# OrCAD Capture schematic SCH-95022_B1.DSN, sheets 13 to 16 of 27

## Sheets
13 Page14 USB3.0 TYPE-C DRP: size C
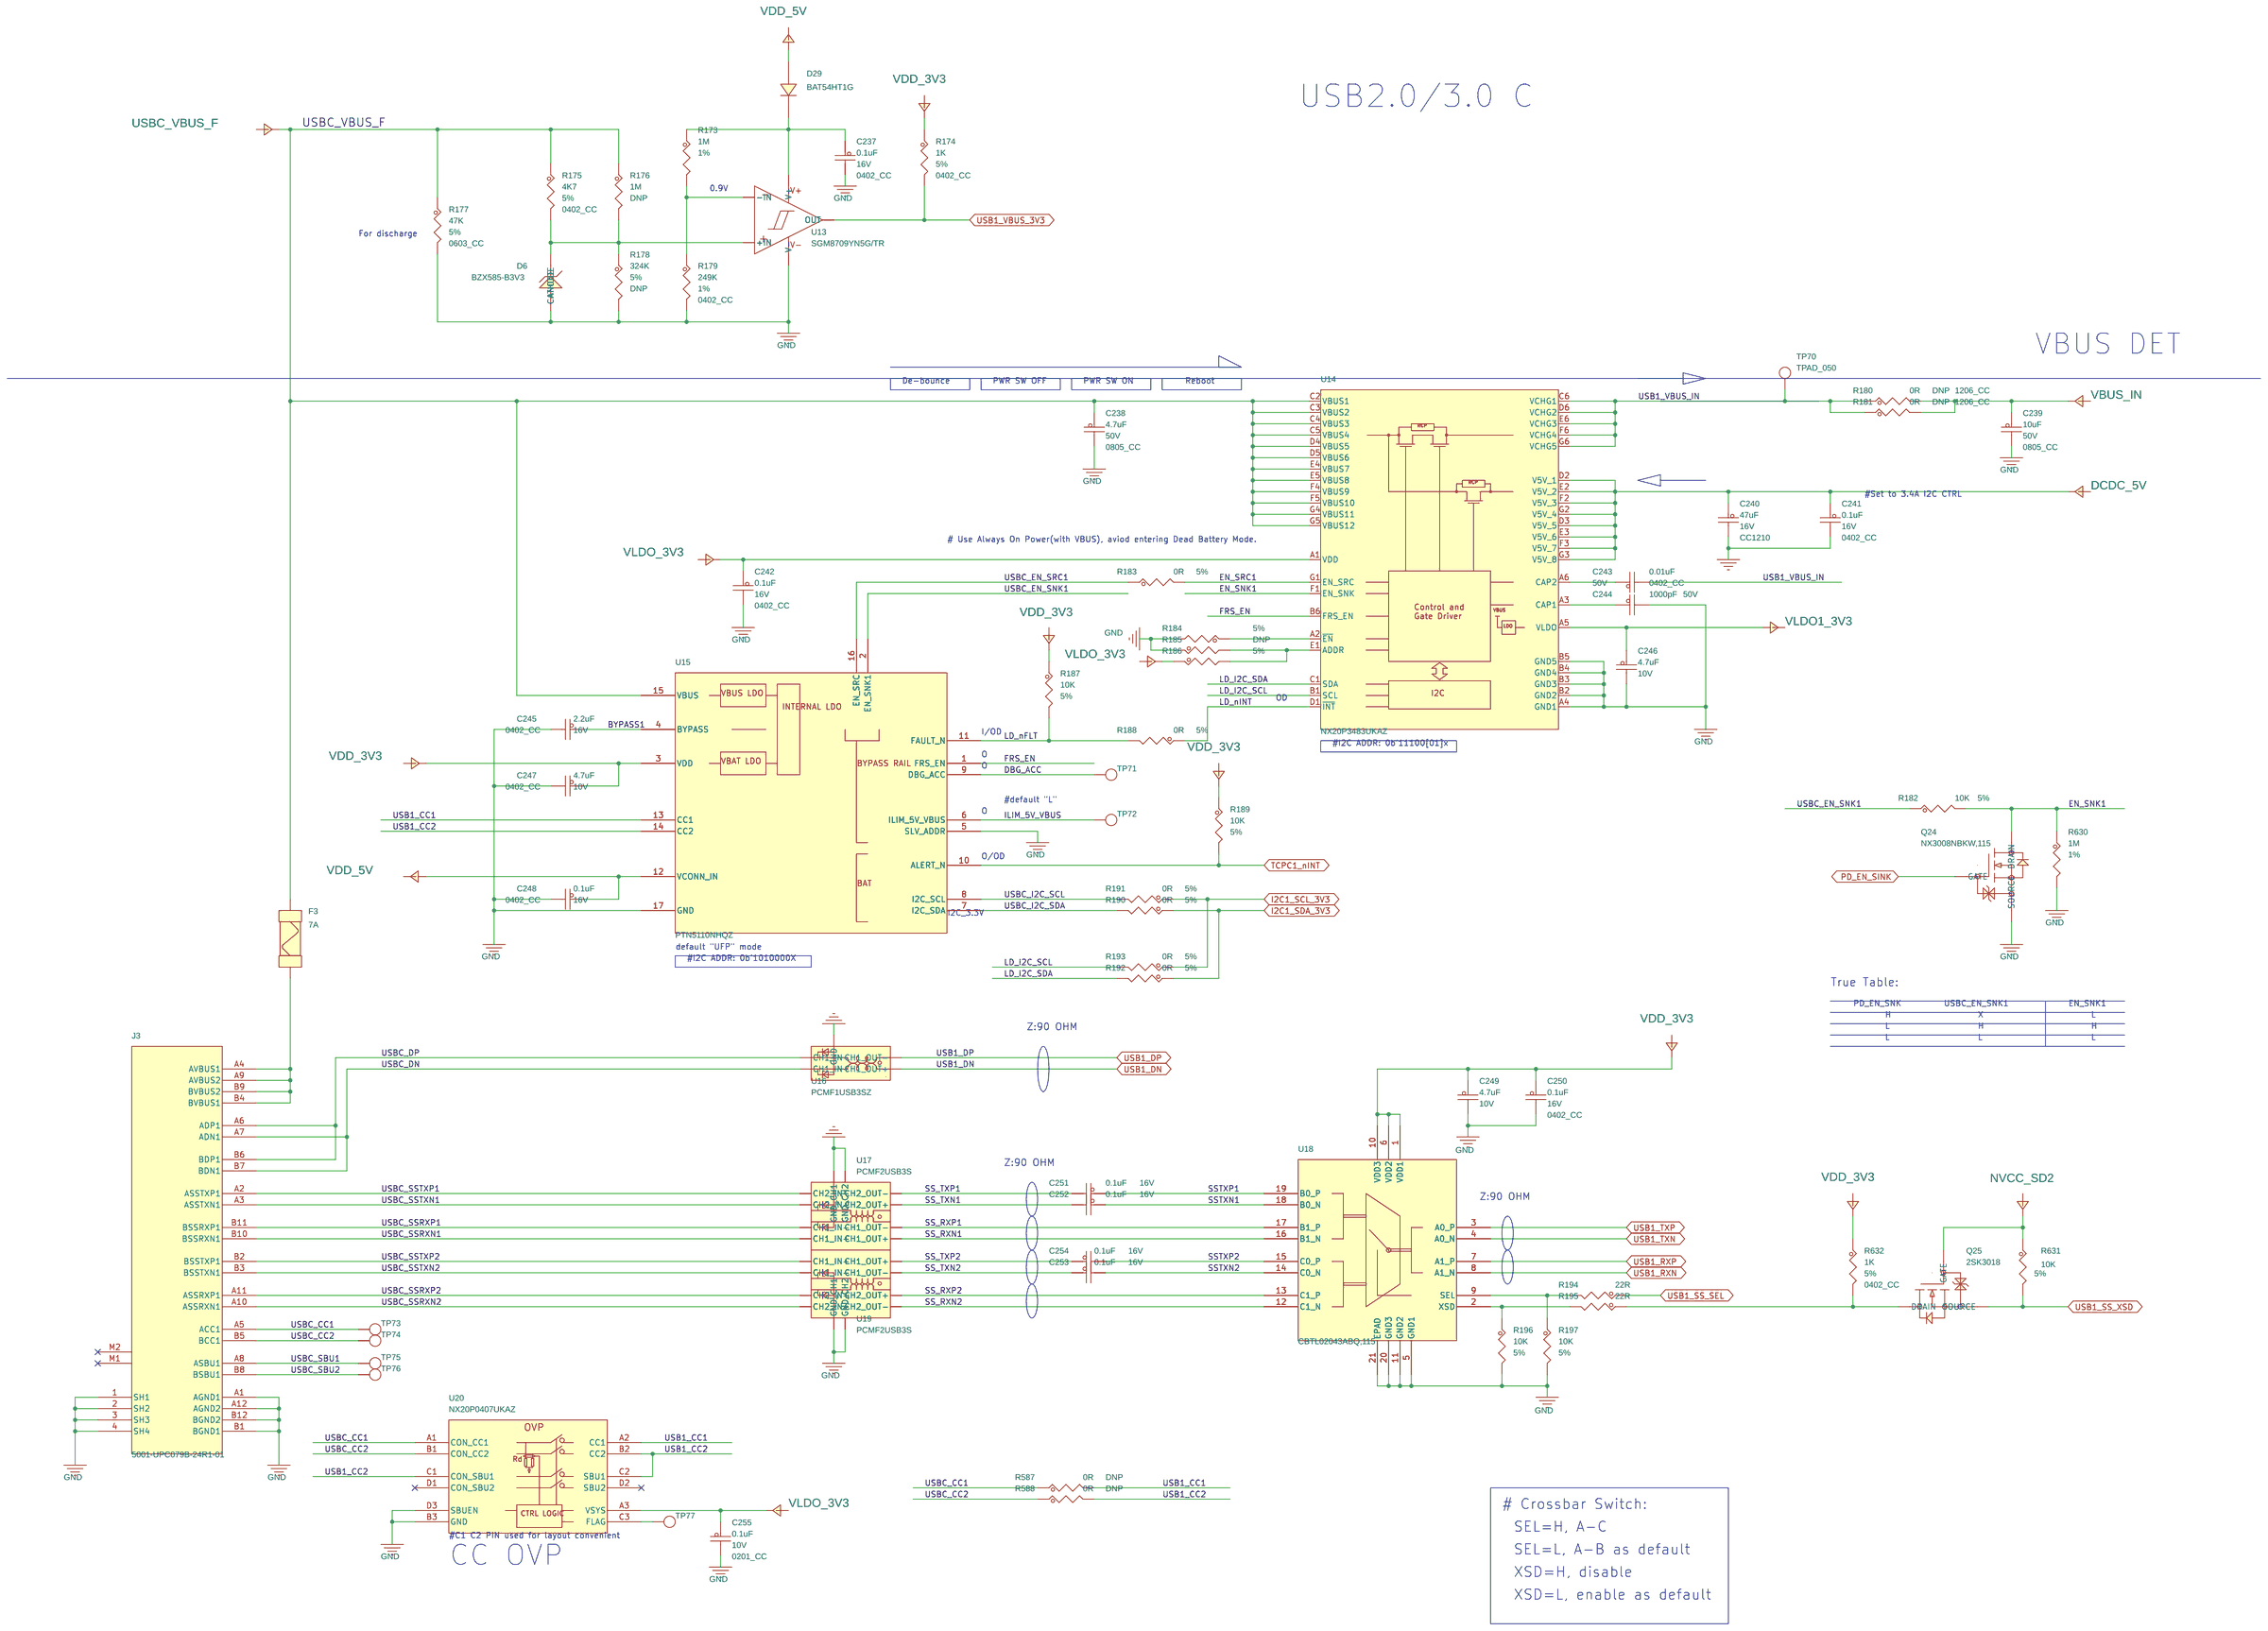
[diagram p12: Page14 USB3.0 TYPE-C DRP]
14 Page15 USB3.0 HOST: size A4
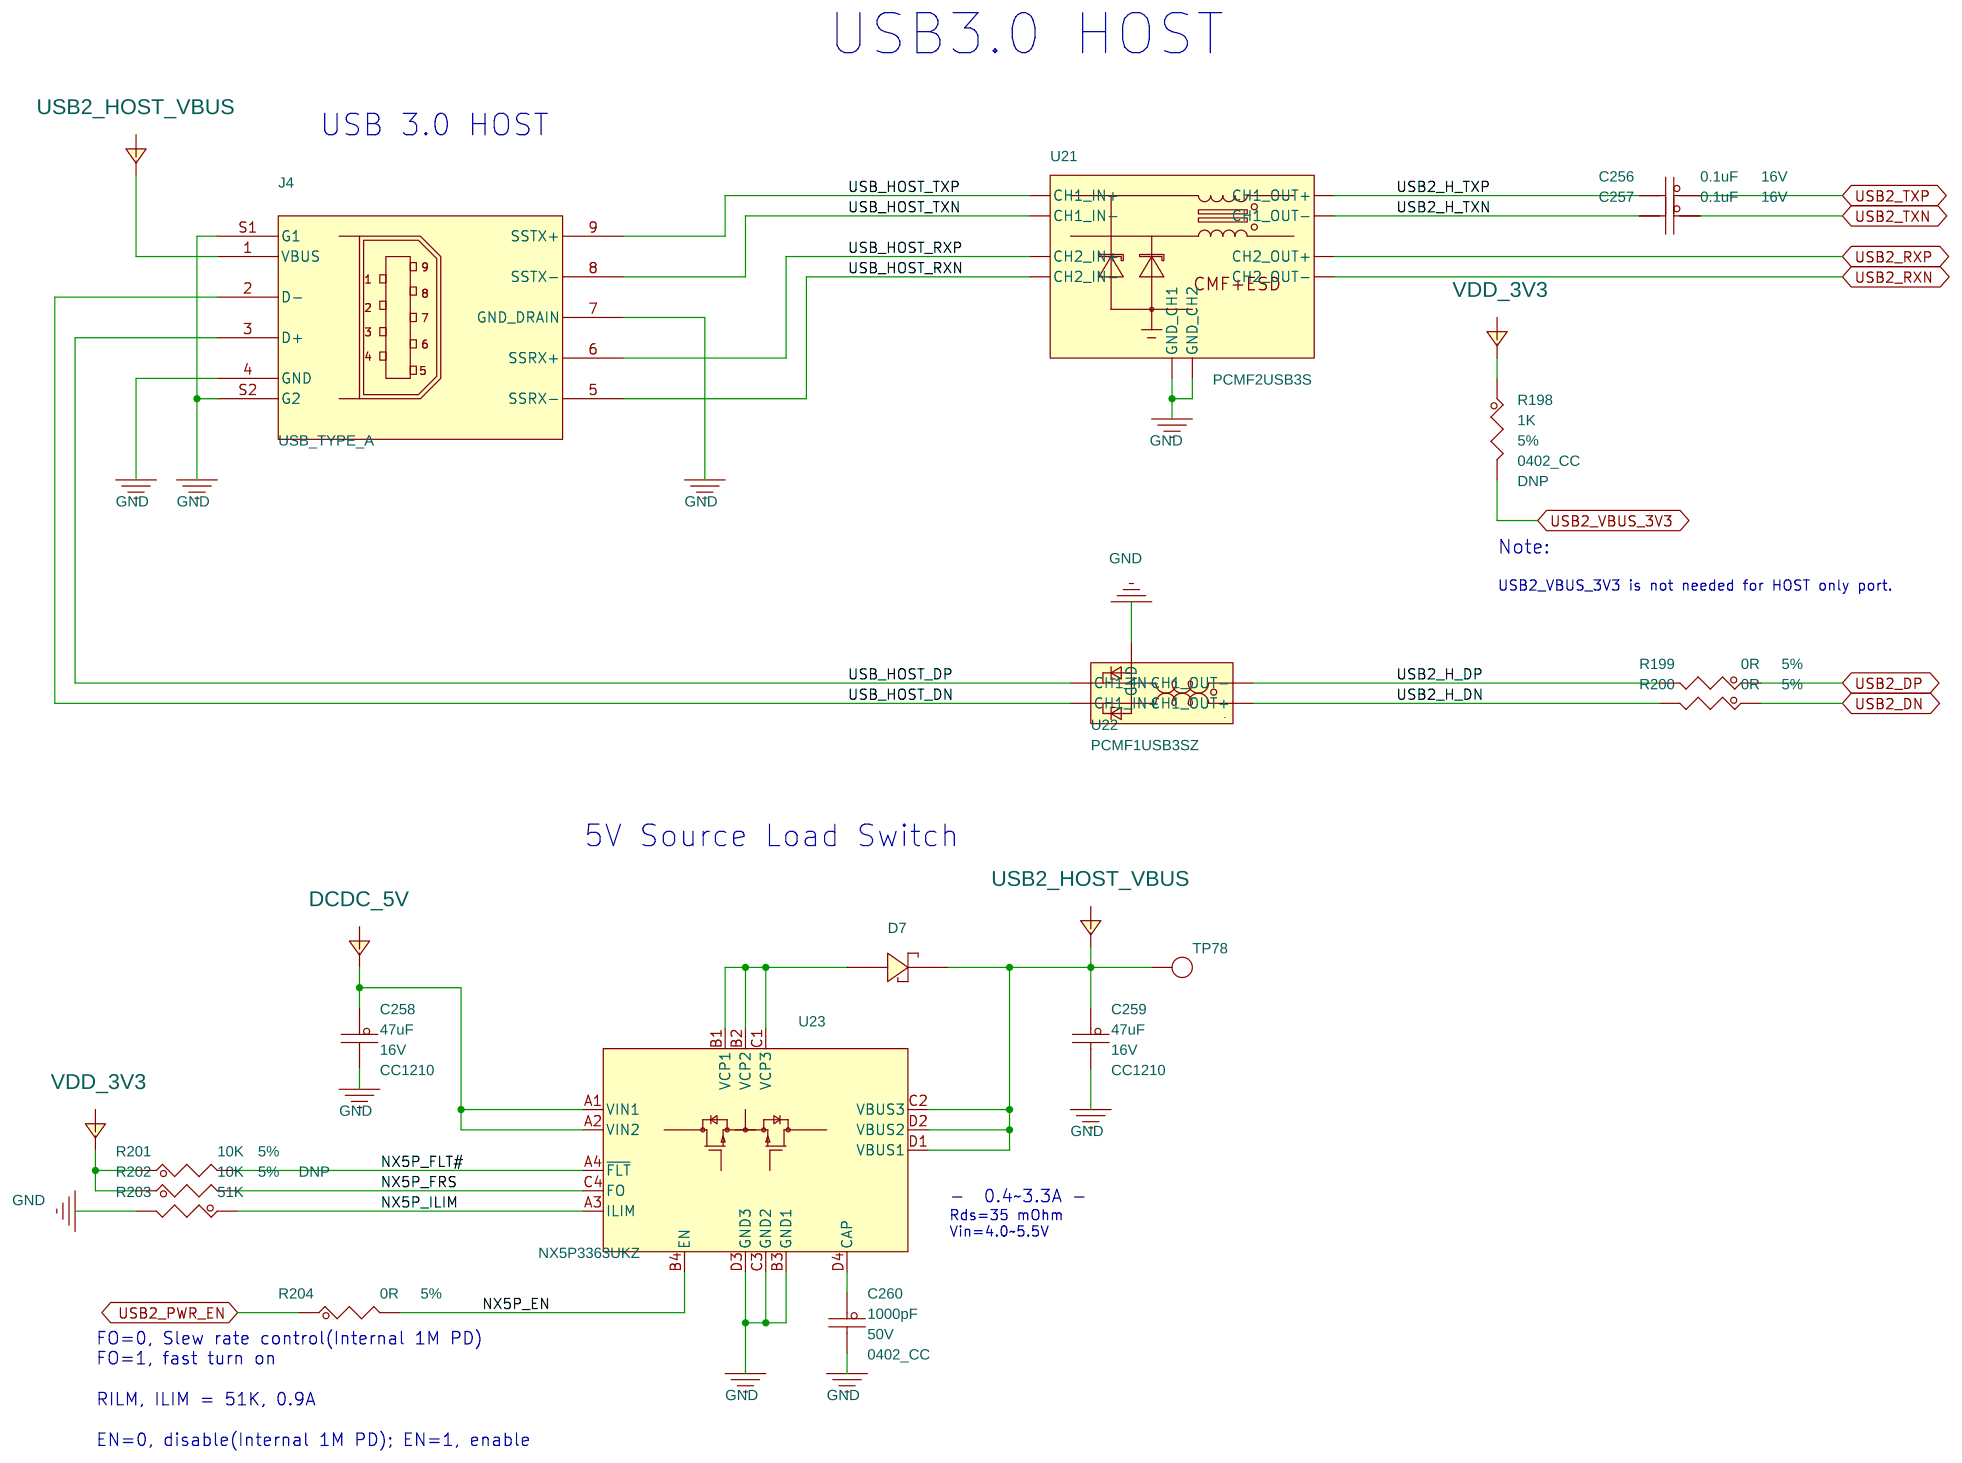
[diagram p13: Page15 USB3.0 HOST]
15 Page16 Giga Ethernet1 POE-PD: size C
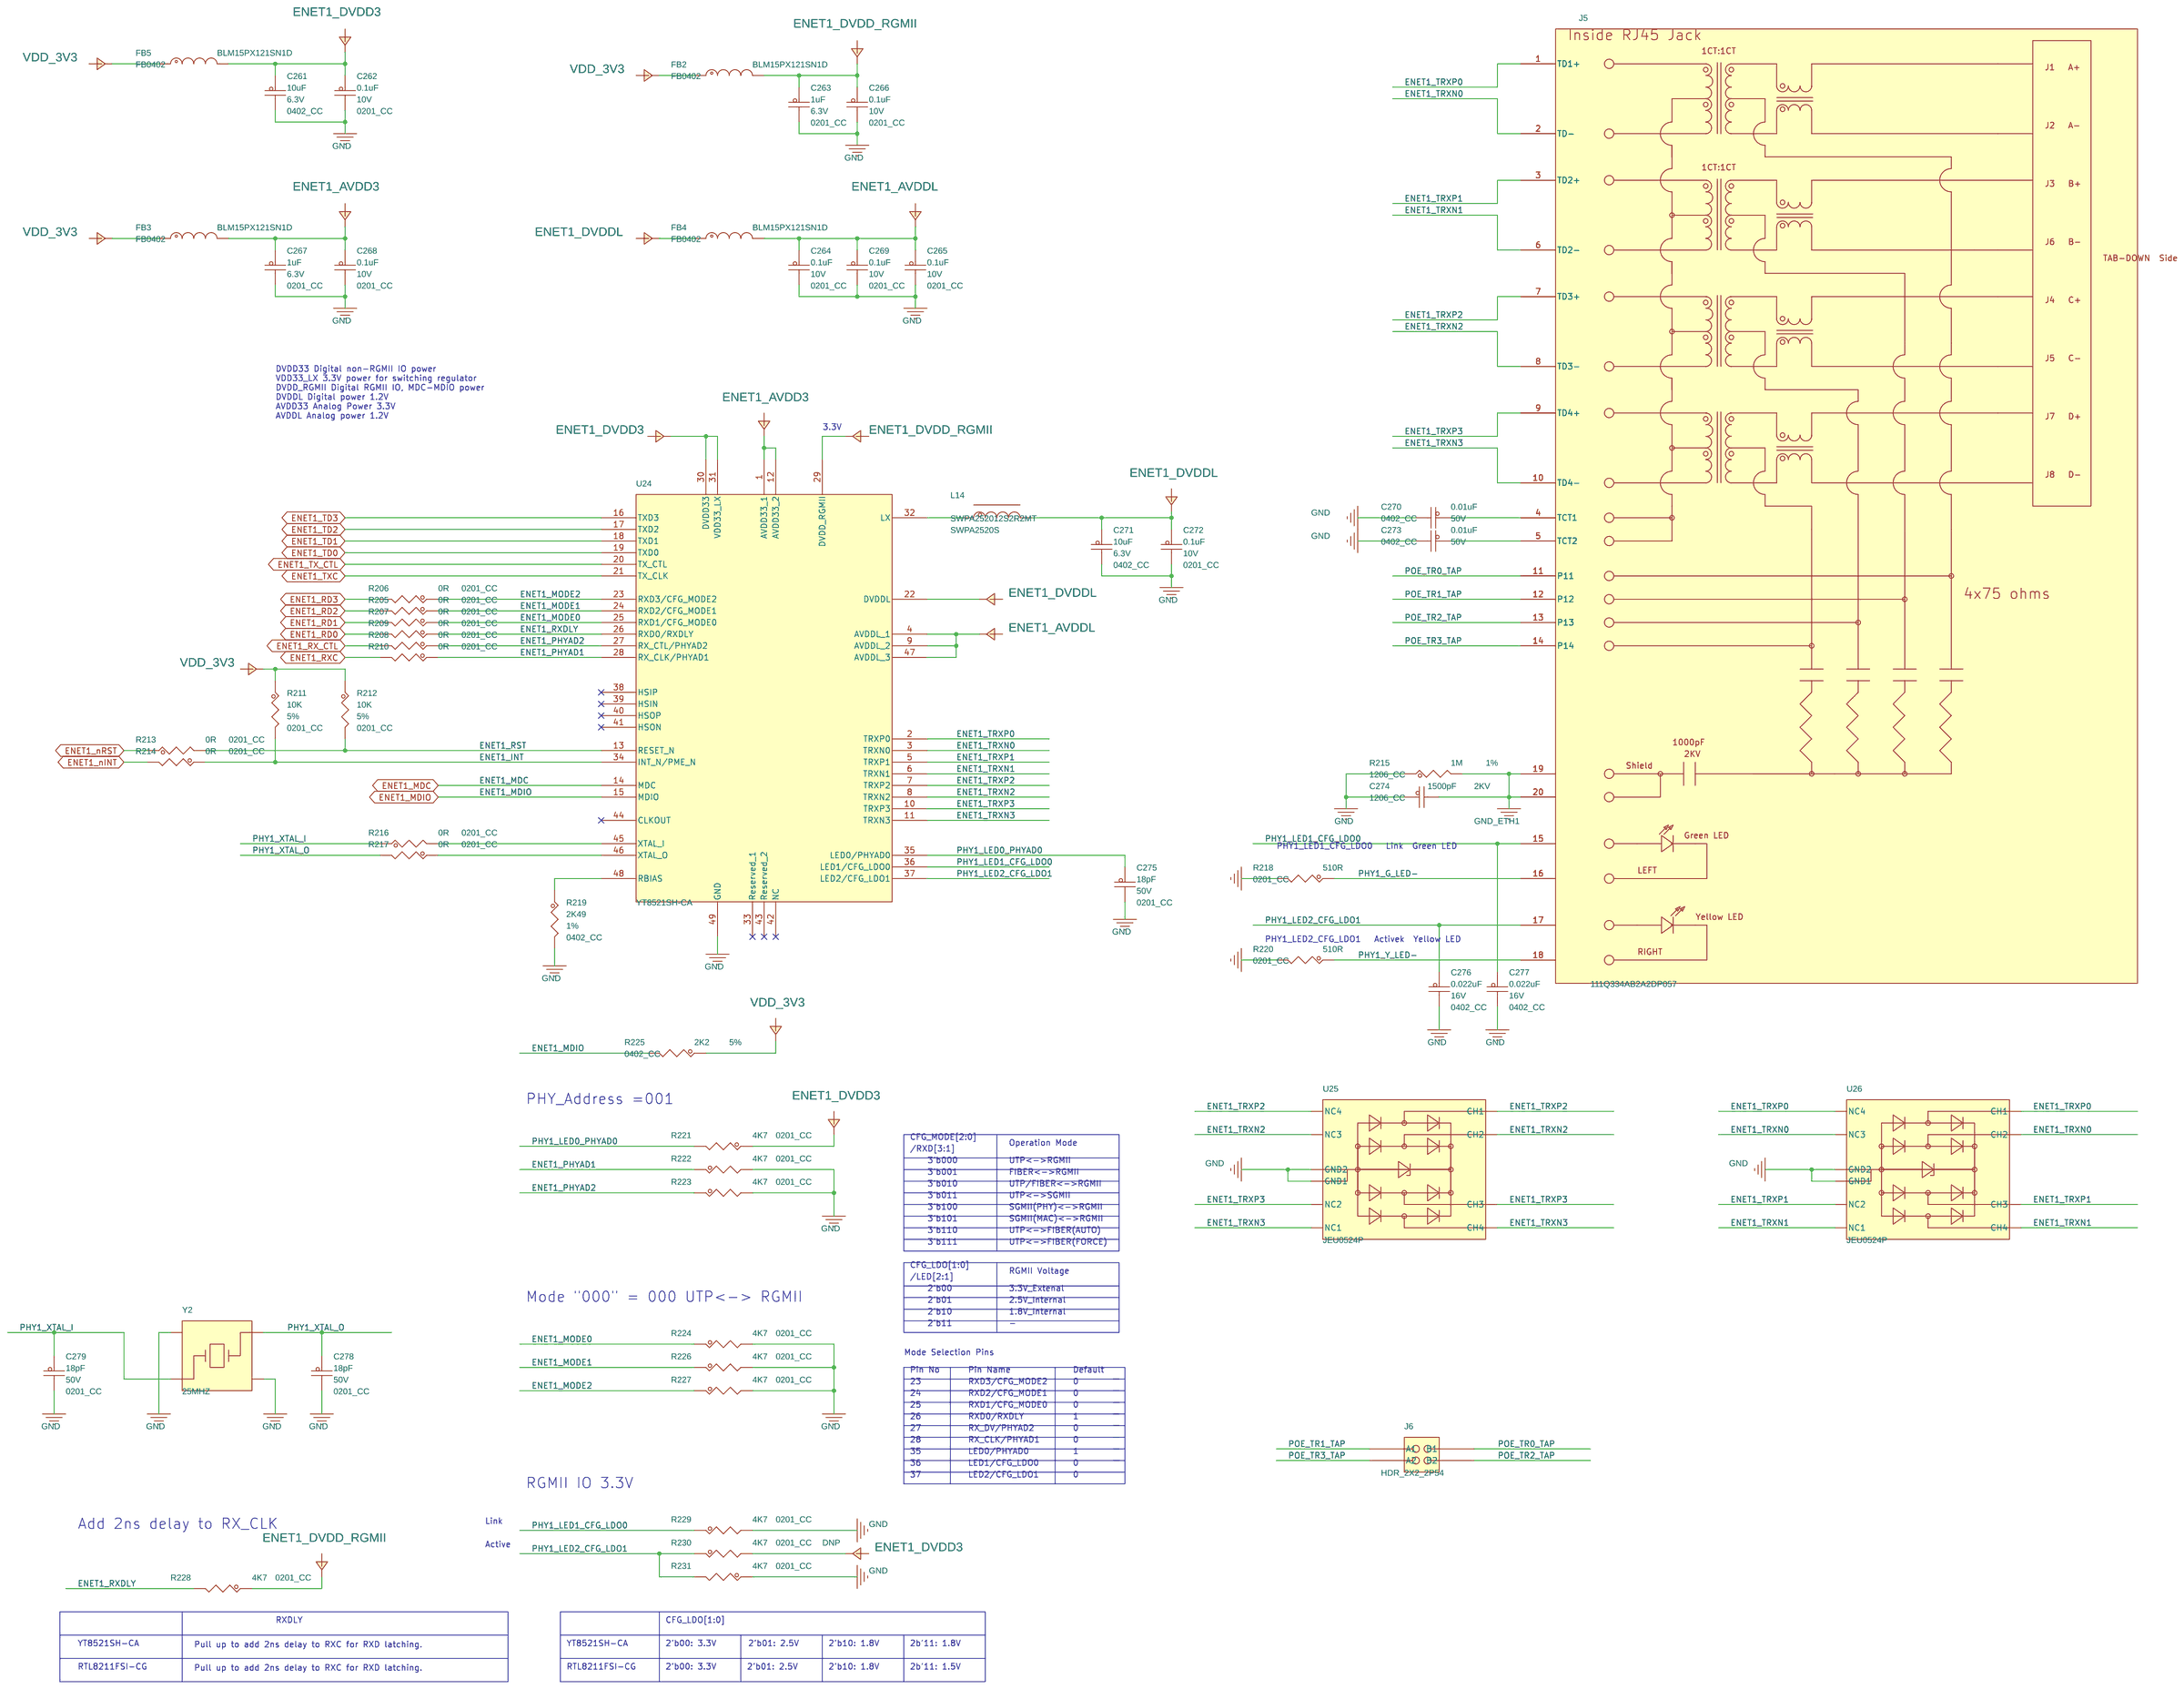
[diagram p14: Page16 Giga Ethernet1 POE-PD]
16 Page17 Giga Ethernet2 TSN: size C
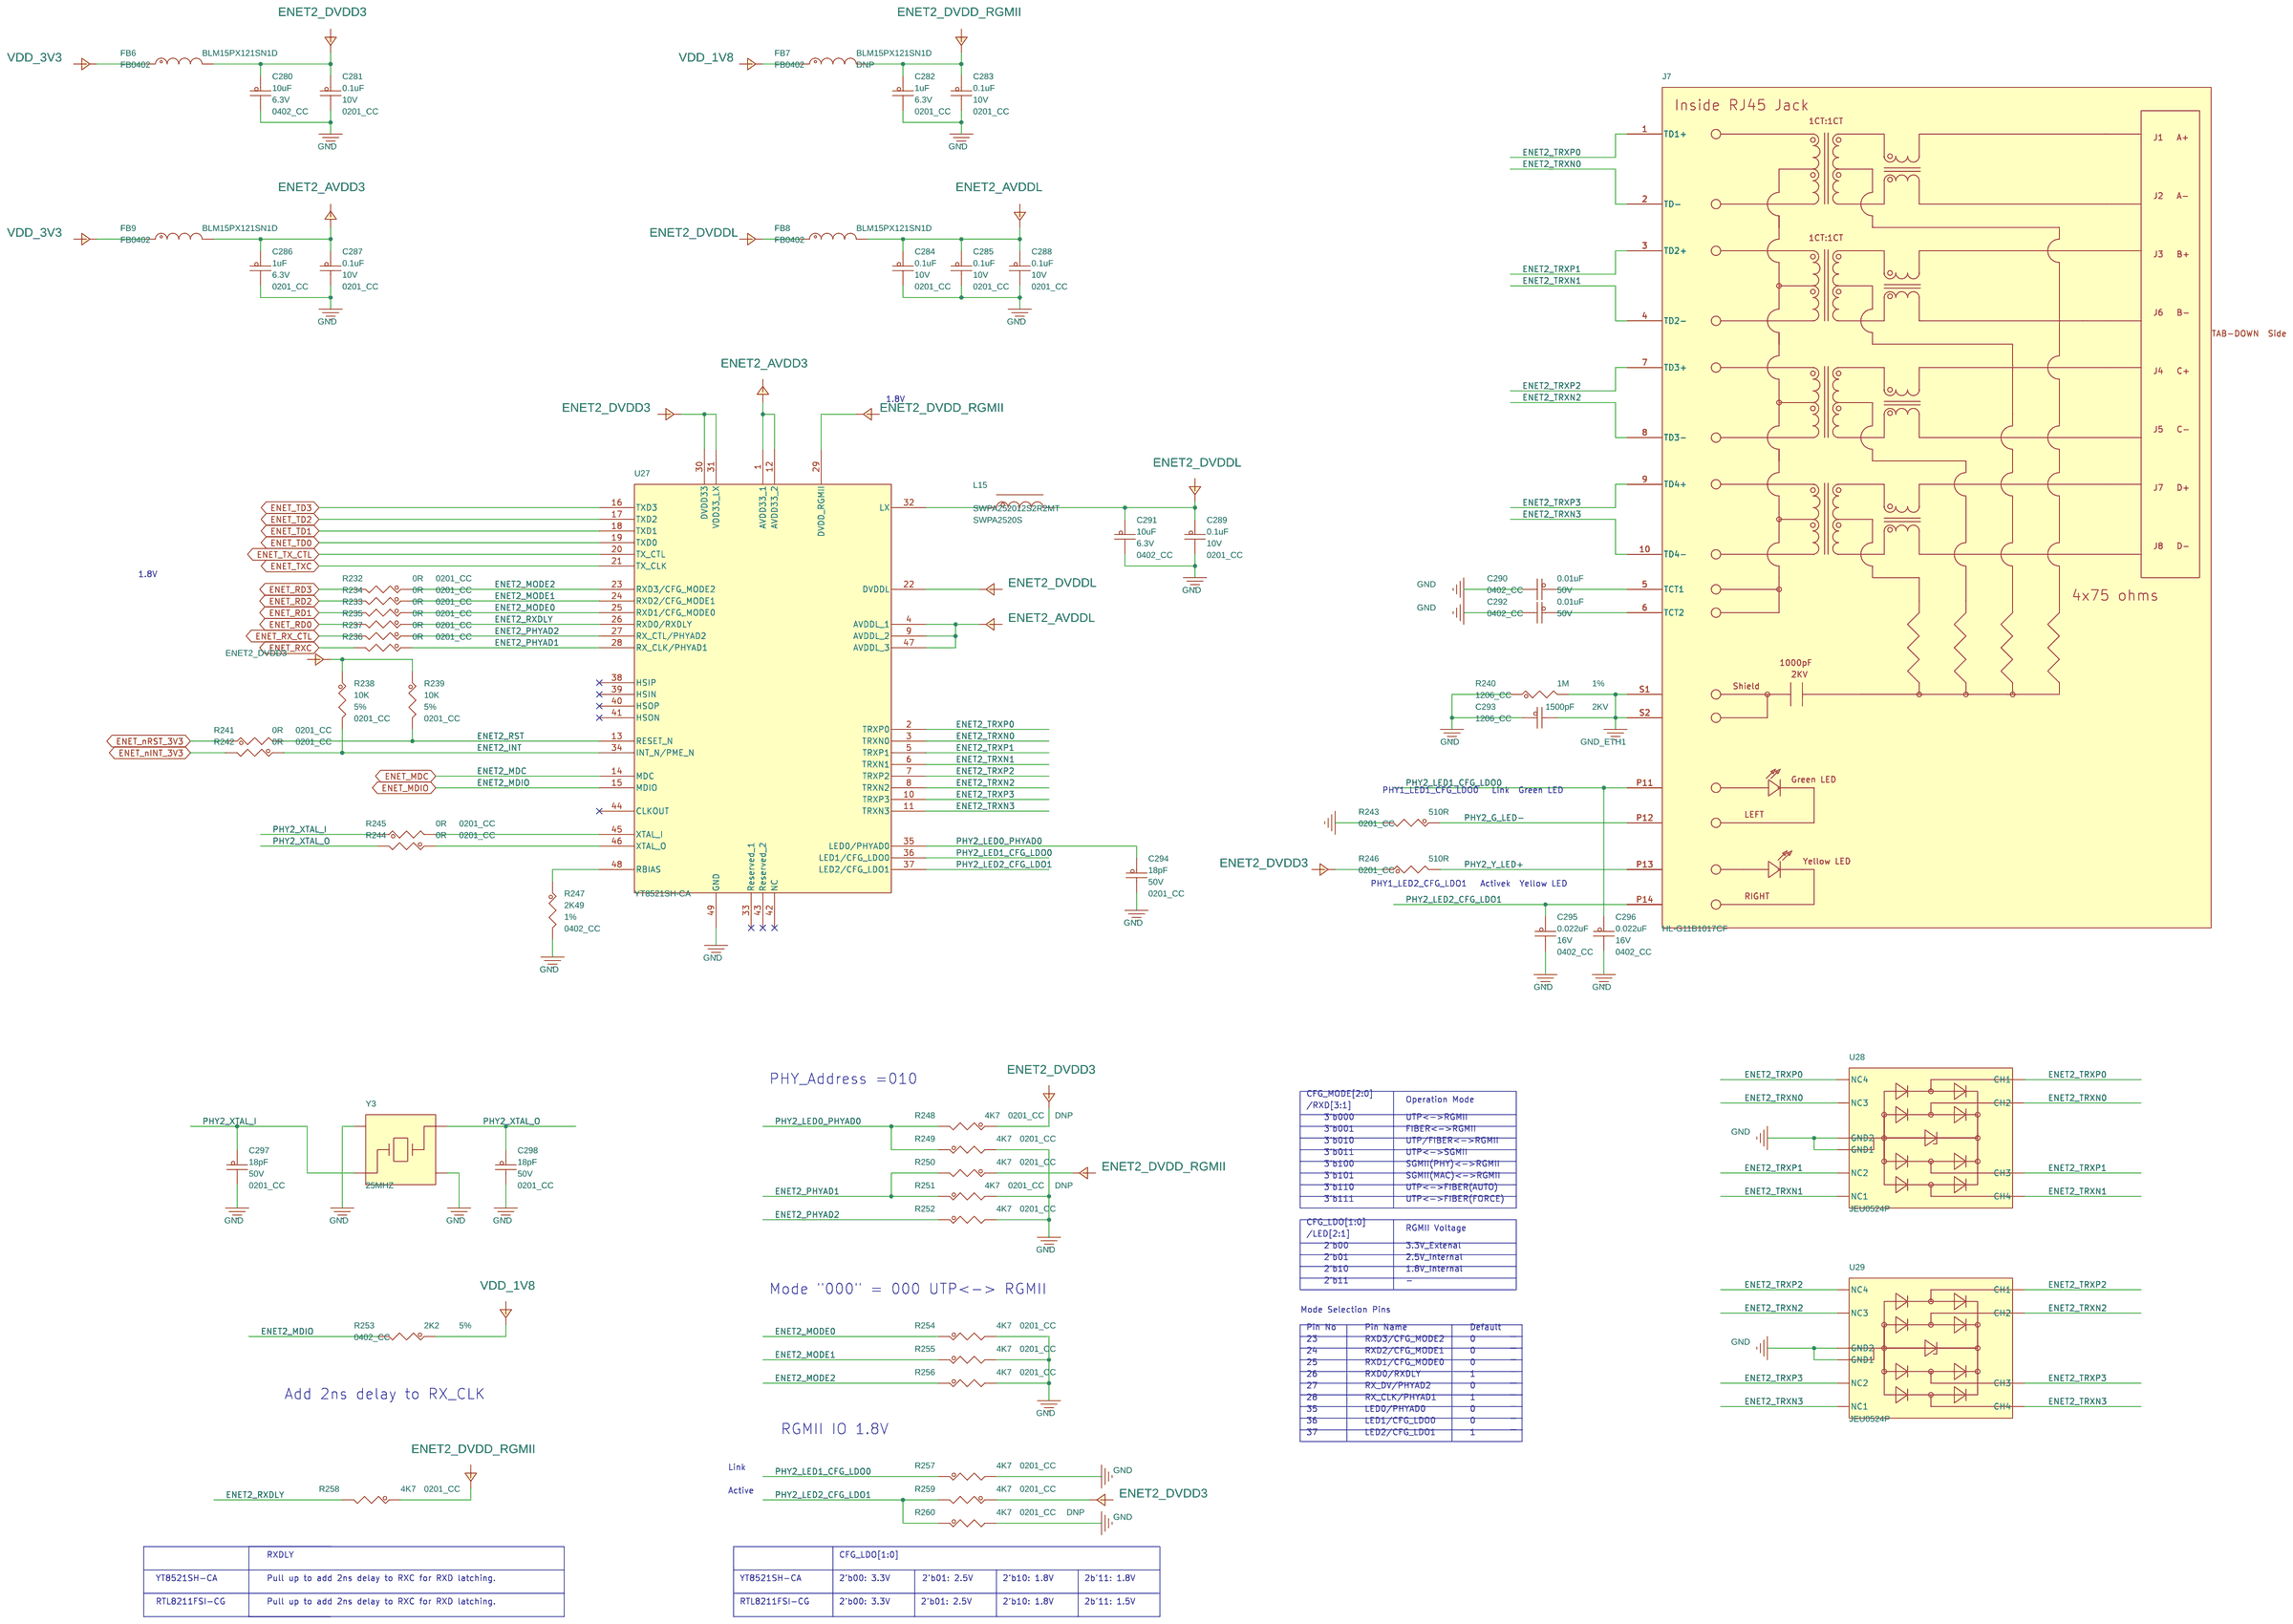
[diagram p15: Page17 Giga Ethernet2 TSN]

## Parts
sheet Page14 USB3.0 TYPE-C DRP
C237  0.1uF  [0402_CC]
C238  4.7uF  [0805_CC]
C239  10uF  [0805_CC]
C240  47uF  [CC1210]
C241  0.1uF  [0402_CC]
C242  0.1uF  [0402_CC]
C243  0.01uF  [0402_CC]
C244  1000pF  [0402_CC]
C245  2.2uF  [0402_CC]
C246  4.7uF  [0402_CC]
C247  4.7uF  [0402_CC]
C248  0.1uF  [0402_CC]
C249  4.7uF  [0402_CC]
C250  0.1uF  [0402_CC]
C251  0.1uF  [0402_CC]
C252  0.1uF  [0402_CC]
C253  0.1uF  [0402_CC]
C254  0.1uF  [0402_CC]
C255  0.1uF  [0201_CC]
D6  BZX585-B3V3  [sod523]
D29  BAT54HT1G  [SOD323]
F3  7A  [fuse_3p4x1p8]
J3  5001-UPC079B-24R1-01  [TYPEC24P_0P50_8R94x7R90x3R16]
Q24  NX3008NBKW,115  [sc70_3]
Q25  2SK3018  [SOT_323]
R173  1M  [0402_CC]
R174  1K  [0402_CC]
R175  4K7  [0402_CC]
R176  1M  [0402_CC]
R177  47K  [0603_CC]
R178  324K  [0402_CC]
R179  249K  [0402_CC]
R180  0R  [1206_CC]
R181  0R  [1206_CC]
R182  10K  [0402_CC]
R183  0R  [0402_CC]
R184  100K  [0402_CC]
R185  100K  [0402_CC]
R186  100K  [0402_CC]
R187  10K  [0402_CC]
R188  0R  [0402_CC]
R189  10K  [0402_CC]
R190  0R  [0402_CC]
R191  0R  [0402_CC]
R192  0R  [0402_CC]
R193  0R  [0402_CC]
R194  22R  [0201_CC]
R195  22R  [0201_CC]
R196  10K  [0402_CC]
R197  10K  [0402_CC]
R587  0R  [0201_CC]
R588  0R  [0201_CC]
R630  1M  [0402_CC]
R631  10K  [0402_CC]
R632  1K  [0402_CC]
TP70  TPAD_050  [TPAD_050]
TP71  TPAD_020  [tpad_020]
TP72  TPAD_020  [tpad_020]
TP73  TPAD_020  [tpad_020]
TP74  TPAD_020  [tpad_020]
TP75  TPAD_020  [tpad_020]
TP76  TPAD_020  [tpad_020]
TP77  TPAD_020  [tpad_020]
U13  SGM8709YN5G/TR  [SOT-23-5]
U14  NX20P3483UKAZ  [wlcsp42_0p4_2p94x2p54_smdp]
U15  PTN5110NHQZ  [hx2qfn16_0p4_2p7x2p7]
U16  PCMF1USB3SZ  [wlcsp5_0p4_0p82x1p22]
U17  PCMF2USB3S  [wlcsp10_0p4_1p2x1p6mm_smdp]
U18  CBTL02043ABQ,115  [dhvqfn20_0p5_2p6x4p6]
U19  PCMF2USB3S  [wlcsp10_0p4_1p2x1p6mm_smdp]
U20  NX20P0407UKAZ  [wlcsp12_0p4_1p3x1p7mm_smdp]
sheet Page15 USB3.0 HOST
C256  0.1uF  [0402_CC]
C257  0.1uF  [0402_CC]
C258  47uF  [CC1210]
C259  47uF  [CC1210]
C260  1000pF  [0402_CC]
D7  B5819W  [sod123lf]
J4  USB_TYPE_A  [con9_usb_16p8x14p2_th]
R198  1K  [0402_CC]
R199  0R  [0402_CC]
R200  0R  [0402_CC]
R201  10K  [0402_CC]
R202  10K  [0402_CC]
R203  51K  [0402_CC]
R204  0R  [0402_CC]
TP78  TPAD_020  [tpad_020]
U21  PCMF2USB3S  [wlcsp10_0p4_1p2x1p6mm_smdp]
U22  PCMF1USB3SZ  [wlcsp5_0p4_0p82x1p22]
U23  NX5P3363UKZ  [bga16_0p5_2p23x2p23]
sheet Page16 Giga Ethernet1 POE-PD
C261  10uF  [0402_CC]
C262  0.1uF  [0201_CC]
C263  1uF  [0201_CC]
C264  0.1uF  [0201_CC]
C265  0.1uF  [0201_CC]
C266  0.1uF  [0201_CC]
C267  1uF  [0201_CC]
C268  0.1uF  [0201_CC]
C269  0.1uF  [0201_CC]
C270  0.01uF  [0402_CC]
C271  10uF  [0402_CC]
C272  0.1uF  [0201_CC]
C273  0.01uF  [0402_CC]
C274  1500pF  [1206_CC]
C275  18pF  [0201_CC]
C276  0.022uF  [0402_CC]
C277  0.022uF  [0402_CC]
C278  18pF  [0201_CC]
C279  18pF  [0201_CC]
FB2  BLM15PX121SN1D  [FB0402]
FB3  BLM15PX121SN1D  [FB0402]
FB4  BLM15PX121SN1D  [FB0402]
FB5  BLM15PX121SN1D  [FB0402]
J5  111Q334AB2A2DP057  [DIP_21R35x15R90x13R65]
J6  HDR_2X2_2P54  [DIP_2P54_2x2]
L14  SWPA252012S2R2MT  [SWPA2520S]
R205  0R  [0201_CC]
R206  0R  [0201_CC]
R207  0R  [0201_CC]
R208  0R  [0201_CC]
R209  0R  [0201_CC]
R210  0R  [0201_CC]
R211  10K  [0201_CC]
R212  10K  [0201_CC]
R213  0R  [0201_CC]
R214  0R  [0201_CC]
R215  1M  [1206_CC]
R216  0R  [0201_CC]
R217  0R  [0201_CC]
R218  510R  [0201_CC]
R219  2K49  [0402_CC]
R220  510R  [0201_CC]
R221  4K7  [0201_CC]
R222  4K7  [0201_CC]
R223  4K7  [0201_CC]
R224  4K7  [0201_CC]
R225  2K2  [0402_CC]
R226  4K7  [0201_CC]
R227  4K7  [0201_CC]
R228  4K7  [0201_CC]
R229  4K7  [0201_CC]
R230  4K7  [0201_CC]
R231  4K7  [0201_CC]
U24  YT8521SH-CA  [QFN48P_0_4BSC_6x6_H]
U25  JEU0524P  [SLP2510P8-10]
U26  JEU0524P  [SLP2510P8-10]
Y2  25MHZ  [xtlosc4_3p2x2p5mm_sm]
sheet Page17 Giga Ethernet2 TSN
C280  10uF  [0402_CC]
C281  0.1uF  [0201_CC]
C282  1uF  [0201_CC]
C283  0.1uF  [0201_CC]
C284  0.1uF  [0201_CC]
C285  0.1uF  [0201_CC]
C286  1uF  [0201_CC]
C287  0.1uF  [0201_CC]
C288  0.1uF  [0201_CC]
C289  0.1uF  [0201_CC]
C290  0.01uF  [0402_CC]
C291  10uF  [0402_CC]
C292  0.01uF  [0402_CC]
C293  1500pF  [1206_CC]
C294  18pF  [0201_CC]
C295  0.022uF  [0402_CC]
C296  0.022uF  [0402_CC]
C297  18pF  [0201_CC]
C298  18pF  [0201_CC]
FB6  BLM15PX121SN1D  [FB0402]
FB7  BLM15PX121SN1D  [FB0402]
FB8  BLM15PX121SN1D  [FB0402]
FB9  BLM15PX121SN1D  [FB0402]
J7  HL-G11B1017CF  [RJ45_21R35x15R95x13R50]
L15  SWPA252012S2R2MT  [SWPA2520S]
R232  0R  [0201_CC]
R233  0R  [0201_CC]
R234  0R  [0201_CC]
R235  0R  [0201_CC]
R236  0R  [0201_CC]
R237  0R  [0201_CC]
R238  10K  [0201_CC]
R239  10K  [0201_CC]
R240  1M  [1206_CC]
R241  0R  [0201_CC]
R242  0R  [0201_CC]
R243  510R  [0201_CC]
R244  0R  [0201_CC]
R245  0R  [0201_CC]
R246  510R  [0201_CC]
R247  2K49  [0402_CC]
R248  4K7  [0201_CC]
R249  4K7  [0201_CC]
R250  4K7  [0201_CC]
R251  4K7  [0201_CC]
R252  4K7  [0201_CC]
R253  2K2  [0402_CC]
R254  4K7  [0201_CC]
R255  4K7  [0201_CC]
R256  4K7  [0201_CC]
R257  4K7  [0201_CC]
R258  4K7  [0201_CC]
R259  4K7  [0201_CC]
R260  4K7  [0201_CC]
U27  YT8521SH-CA  [QFN48P_0_4BSC_6x6_H]
U28  JEU0524P  [SLP2510P8-10]
U29  JEU0524P  [SLP2510P8-10]
Y3  25MHZ  [xtlosc4_3p2x2p5mm_sm]

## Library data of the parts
C237 C241 C242 C248 C250-C254 C256 C257 = CAP_NP: CAP CER 0.1UF 16V 10% X5R 0402; CAD_APPROVED: Yes; FPLIST: CC0402_25,CC0402_HD,0402_CC,capc0402_l; HEIGHT: 0.55MM; MFG_NAME01: SAMSUNG; MFG_PN01: CL05B104K05NNNC; Polyhex_Number: PD.005.0036; ROHS: Yes; Tolerance: 10%; VOLTAGE: 16V
C238 = CAP_NP: CAP CER 4.7UF 50V 10% X5R 0805; CAD_APPROVED: Yes; MFG_NAME01: SAMSUNG; MFG_PN01: CL21A475KBQNNNE; Polyhex_Number: PD.005.0064; ROHS: Yes; Tolerance: 10%; VOLTAGE: 50V
C239 = CAP_NP: CAP CER 10UF 50V 10% X5R 0805; CAD_APPROVED: Yes; MFG_NAME01: SAMSUNG; MFG_PN01: CL21A106KBYQNNE; Polyhex_Number: PD.005.0060; ROHS: Yes; Tolerance: 10%; VOLTAGE: 50V
C240 C258 C259 = CAP_NP: CAP CER 47UF 16V 10% X5R 1210; CAD_APPROVED: Yes; HEIGHT: 2.7 mm; MFG_NAME01: SAMSUNG; MFG_PN01: CL32A476KOJNNNE; Polyhex_Number: PD.005.0133; ROHS: Yes; Tolerance: 10%; VOLTAGE: 16V
C243 C270 C273 C290 C292 = CAP_NP: CAP CER 0.01uF 50V 10% X7R 0402; CAD_APPROVED: Yes; FPLIST: CC0402_25,CC0402_HD,0402_CC,capc0402_l; HEIGHT: 0.55 MM; MFG_NAME01: SAMSUNG; MFG_PN01: CL05B103KB5NNNC; Package Size: 0402; Polyhex_Number: PD.005.0006; ROHS: Yes; Tolerance: 10%; VOLTAGE: 50V
C244 C260 = CAP_NP: CAP CER 1000PF 50V 5% C0G 0402; AGILE_PN: 150-76334; CAD_APPROVED: Yes; FPLIST: CC0402_25,CC0402_HD,0402_CC,capc0402_l; HEIGHT: 0.55MM; MFG_NAME01: SAMSUNG; MFG_PN01: CL05B102KB5NNNC; Package Size: 0402; Package Type: 180mm Paper Tape; Polyhex_Number: PD.005.0076; ROHS: Yes; Tolerance: 5%; VOLTAGE: 50V
C245 = CAP_NP: CAP CER 2.2uF 10V 10% X5R 0402; CAD_APPROVED: Yes; FPLIST: CC0402_25,CC0402_HD,0402_CC,capc0402_l; HEIGHT: 0.55 MM; MFG_NAME01: SAMSUNG; MFG_PN01: CL05A225KO5NQNC; Package Size: 0402; Polyhex_Number: PD.005.0041; ROHS: Yes; Tolerance: 10%; VOLTAGE: 16V
C246 C247 C249 = CAP_NP: CAP CER 4.7uF 10V 10% X5R 0402; CAD_APPROVED: Yes; HEIGHT: 0.95MM; MFG_NAME01: SAMSUNG; MFG_PN01: CL05A475KP5NRNC; Polyhex_Number: PD.005.0058; ROHS: Yes; Temp Range: -55°C to + 85°C; Tolerance: 10%; VOLTAGE: 10V
C255 C262 C264-C266 C268 C269 C272 C281 C283-C285 C287-C289 = CAP_NP: CAP CER 0.1uF 10V 20% X5R 0201; CAD_APPROVED: Yes; HEIGHT: 0.35MM; MFG_NAME01: SAMSUNG; MFG_PN01: CL03A104KP3NNNC; Package Size: 0201; Package Type: 7” reel; Polyhex_Number: PD.005.0054; ROHS: Yes; Tolerance: 20%; VOLTAGE: 10V
D6 = ZDIODE: DIODE ZNR 0.3W 3.3V 200mA AEC-Q101 SOD-523; AGILE_PN: 480-79870; CAD_APPROVED: Yes; HEIGHT: 0.65MM; MFG_NAME01: NEXPERIA; Polyhex_Number: PD.020.0074; ROHS: Yes; Temp Range: -65°C to +150°C; Temp_Range: -65°C to +150°C
D29 = DIODE: DIODE SCH 30V 200MA -- SOD323; AGILE_PN: 480-30039; CAD_APPROVED: Yes; HEIGHT: 1.15MM; MFG_NAME01: ON SEMICONDUCTOR; Polyhex_Number: PD.020.0073
F3 = FUSE: FUSE HIGH I2T 7A 32V 1206; AGILE_PN: 510-77913; CAD_APPROVED: Yes; HEIGHT: 0.8639MM; MFG_NAME01: LITTELFUSE; MFG_PN01: 0440007.WR; Polyhex_Number: PD.004.0322; ROHS: Yes
J3 = TYPE-C_24p: CON 24PIN USB TYPE C SMT; MFG_NAME01: WENZHANGJIMEI; Polyhex_Number: PD.010.0028; Temp Range: -30C to +80C; Temp_Range: -30C to +80C
Q24 = NX3008NBKW_SOT323: TRAN NMOS SW 30V 350mA AEC-Q101 SC-70; AGILE_PN: 480-79736; CAD_APPROVED: Yes; HEIGHT: 1.1MM; MFG_NAME01: NEXPERIA; Polyhex_Number: PD.014.0033; ROHS: Yes
Q25 = 2SK3018_SOT323: NMOS SW 30V 100mA SOT-323; MFG_NAME01: CHANGJING ELECTRONICS; Polyhex_Number: PD.014.0008
R173 R630 = RES: RES MF 1M 1/16W 1% 0402; AGILE_PN: 470-80575; CAD_APPROVED: Yes; FPLIST: RC0402_25,RC0402_HD,0402_CC; HEIGHT: 0.4MM; MFG_NAME01: YAGEO; MFG_PN01: RC0402FR-071ML; Polyhex_Number: PD.004.0230; ROHS: Yes; Tolerance: 1%
R174 R632 = RES: RES MF 1K 1/16W 5% 0402; CAD_APPROVED: Yes; HEIGHT: 0.4 MM; MFG_NAME01: YAGEO; MFG_PN01: RC0402JR-071KL; Polyhex_Number: PD.004.0007; ROHS: Yes; Tolerance: 5%
R175 = RES: RES MF 4K7 1/16W 5% 0402; AGILE_PN: 470-75557; CAD_APPROVED: Yes; HEIGHT: 0.4 MM; MFG_NAME01: YAGEO; MFG_PN01: RC0402JR-074K7L; Polyhex_Number: PD.004.0006; ROHS: Yes; Tolerance: 5%; VOLTAGE: 50V
R176 = RES: RES MF 1M 1/16W 1% 0402; AGILE_PN: 470-80575; ASSY_OPT: DNP; CAD_APPROVED: Yes; FPLIST: RC0402_25,RC0402_HD,0402_CC; HEIGHT: 0.4MM; MFG_NAME01: YAGEO; MFG_PN01: RC0402FR-071ML; Polyhex_Number: PD.004.0230; ROHS: Yes; Tolerance: 1%
R177 = RES: RES MF 47K 1/10W 5% 0603; AGILE_PN: 470-75557; CAD_APPROVED: Yes; HEIGHT: 0.4 MM; MFG_NAME01: YAGEO; MFG_PN01: RC0603JR-0747KL; Polyhex_Number: PD.004.0329; ROHS: Yes; Tolerance: 5%; VOLTAGE: 75V
R178 = RES: RES MF 324K 1/16W 5% 0402; AGILE_PN: 470-80575; ASSY_OPT: DNP; CAD_APPROVED: Yes; FPLIST: RC0402_25,RC0402_HD,0402_CC; HEIGHT: 0.4MM; MFG_NAME01: YAGEO; MFG_PN01: RC0402JR-07324KL; Polyhex_Number: PD.018.xxxx; ROHS: Yes; Tolerance: 5%; VOLTAGE: 50V
R179 = RES: RES MF 249K 1/16W 1% 0402; CAD_APPROVED: Yes; HEIGHT: 0.4 MM; MFG_NAME01: YAGEO; MFG_PN01: RC0402FR-07249KL; Polyhex_Number: PD.004.0187; ROHS: Yes; Tolerance: 1%; VOLTAGE: 50V
R180 R181 = RES: RES MF ZERO OHM JUMPER 1/4W 5% 1206; ASSY_OPT: DNP; CAD_APPROVED: Yes; HEIGHT: 0.6MM; MFG_NAME01: YAGEO; MFG_PN01: RC1206FR-070RL; Polyhex_Number: PD.004.0214; ROHS: Yes; Temp Range: -55 °C to +155 °C; Temp_Range: -55 °C to +155 °C; Tolerance: 5%; VOLTAGE: 200V
R182 R187 R189 R196 R197 R201 R631 = RES: RES MF 10K 1/16W 5% 0402; AGILE_PN: 470-75557; CAD_APPROVED: Yes; FPLIST: RC0402_25,RC0402_HD,0402_CC; HEIGHT: 0.4 MM; MFG_NAME01: YAGEO; MFG_PN01: RC0402JR-0710KL; Polyhex_Number: PD.004.0010; ROHS: Yes; Tolerance: 5%; VOLTAGE: 50V
R183 R188 R190-R193 R199 R200 R204 = RES: RES MF ZERO OHM 1/16W 5% 0402; AGILE_PN: 470-75394; CAD_APPROVED: Yes; FPLIST: RC0402_25,RC0402_HD,RC0402_X2,0402_CC; HEIGHT: 0.45 MM; MFG_NAME01: YAGEO; MFG_PN01: RC0402JR-070RL; Polyhex_Number: PD.004.0009; ROHS: Yes; Tolerance: 5%; VOLTAGE: 50V
R184 R186 = RES: RES MF 100K 1/16W 5% 0402; AGILE_PN: 470-75597; CAD_APPROVED: Yes; FPLIST: RC0402_25,RC0402_HD,0402_CC; HEIGHT: 0.40 MM; MFG_NAME01: YAGEO; MFG_PN01: RC0402JR-07100KL; Polyhex_Number: PD.004.0004; ROHS: Yes; Temp Range: -55C to +155C; Temp_Range: -55C to +155C; Tolerance: 5%; VOLTAGE: 50V
R185 = RES: RES MF 100K 1/16W 5% 0402; AGILE_PN: 470-75597; ASSY_OPT: DNP; CAD_APPROVED: Yes; FPLIST: RC0402_25,RC0402_HD,0402_CC; HEIGHT: 0.40 MM; MFG_NAME01: YAGEO; MFG_PN01: RC0402JR-07100KL; Polyhex_Number: PD.004.0004; ROHS: Yes; Temp Range: -55C to +155C; Temp_Range: -55C to +155C; Tolerance: 5%; VOLTAGE: 50V
R194 R195 = RES: RES MF 22 OHM 1/20W 5% 0201; AGILE_PN: 470-82323; CAD_APPROVED: Yes; FPLIST: RC0201,0201_CC; HEIGHT: 0.26MM; MFG_NAME01: YAGEO; MFG_PN01: RC0201JR-0722RL; Polyhex_Number: PD.004.0173; ROHS: Yes; Temp Range: -55°C ~ 125°C; Temp_Range: -55°C ~ 125°C; Tolerance: 5%; VOLTAGE: 25V
R587 R588 = RES: RES MF ZERO OHM 1/20W 5% 0201; AGILE_PN: 470-82323; ASSY_OPT: DNP; CAD_APPROVED: Yes; FPLIST: RC0201,0201_CC; HEIGHT: 0.26MM; MFG_NAME01: YAGEO; MFG_PN01: RC0201JR-070RL; Polyhex_Number: PD.004.0171; ROHS: Yes; Temp Range: -55°C ~ 125°C; Temp_Range: -55°C ~ 125°C; Tolerance: 5%; VOLTAGE: 25V
TP70 = TESTLOOP: TEST POINT PAD 50MIL DIA SMT, NO PART TO ORDER; AGILE_PN: 211-76644; ASSY_OPT: DNP; CAD_APPROVED: Yes; HEIGHT: 0.1MM; MFG_NAME01: NOTACOMPONENT; MFG_PN01: NOTACOMPONENT; Polyhex_Number: TEST POINT; ROHS: Yes
TP71-TP78 = TESTLOOP: TEST POINT PAD 0.5MM DIA SMT, NO PART TO ORDER; AGILE_PN: 211-77484; ASSY_OPT: DNP; CAD_APPROVED: Yes; HEIGHT: 0.1MM; MFG_NAME01: NOT A COMPONENT; MFG_PN01: NOT A COMPONENT; Polyhex_Number: TEST POINT; ROHS: Yes
U13 = SGM8709YN5G: IC COMP MICRO POWER RAIL TO RAIL INPUT 1.4-5.5V SOT23-5; AGILE_PN: 315-81470; CAD_APPROVED: Yes; HEIGHT: 1.25MM; MFG_NAME01: SG MICRO CORP; Polyhex_Number: PD.008.0309; ROHS: Yes; Temp Range: -40C to +85C; Temp_Range: -40C to +85C; VOLTAGE: 1.4-5.5V
U14 = NX20P3483UK_42P: IC USB PD/TYPE-C PWR Sink/Source Combo SW 5A 2.8-20V WLCSP42; AGILE_PN: 315-81752; CAD_APPROVED: Yes; HEIGHT: 0.565MM; MFG_NAME01: NXP SEMICONDUCTORS; PRE_APN: 315-81752; Polyhex_Number: PD.008.0310; ROHS: Yes; Temp_Range: -40C to +85C
U15 = PTN5110_QFN16: IC USB PD PHY 1PORT 2.7-5.5V HX2QFN16; AGILE_PN: 315-81118; CAD_APPROVED: Yes; HEIGHT: 0.4MM; MFG_NAME01: NXP SEMICONDUCTORS; Polyhex_Number: PD.008.0307; ROHS: Yes; Temp Range: ¨C40C to +85C; Temp_Range: ¨C40C to +85C; VOLTAGE: 2.7-5.5V
U16 U22 = PESD1USB30_5P: IC EMI FILTER ESD PROTECTION 15kV/LINE WLCSP5; 3D_Mechanical_Footprint_File: http://fcl.am.freescale.net/ALLEGRO/step/wlcsp5_0p4_0p82x1p22.STEP; AGILE_PN: 315-84061; CAD_APPROVED: Yes; HEIGHT: 0.6MM; MFG_NAME01: NEXPERIA; Polyhex_Number: PD.008.0311; ROHS: Yes
U17 U19 = PCMF2USB3S_1: IC EMI FILTER FOR DIFF CH W/ ESD PROTECTION 5V WLCSP10; AGILE_PN: 315-81227; CAD_APPROVED: Yes; HEIGHT: 0.6MM; MFG_NAME01: NEXPERIA; Polyhex_Number: PD.008.0312; ROHS: Yes; VOLTAGE: 5V
U18 = CBTL02043ABQ_20P_A: IC CLK DIFF MUX/DEMUX 3.3V DHVQFN20; AGILE_PN: 312-80308; CAD_APPROVED: Yes; HEIGHT: 1MM; MFG_NAME01: NXP SEMICONDUCTORS; Polyhex_Number: PD.008.0313; ROHS: Yes
U20 = NX20P0407_WLCSP12_A: IC USB TYPE C PROTECTION +15KV/+8KV ESD WLCSP12; AGILE_PN: TMP-WF-31350; CAD_APPROVED: Yes; HEIGHT: 0.565 MM; MFG_NAME01: NXP SEMICONDUCTORS; PRE_APN: 312-81846; Polyhex_Number: PD.008.0308; ROHS: Yes; Temp Range: -40C to +85C; VOLTAGE: +15KV/+8KV
D7 = DIODE_SCHTKY: B5819W SCHOTTKY BARRIER DIODE SOD123LF; AGILE_PN: 480-30006; CAD_APPROVED: Yes; EN: 106-2-00107; FPLIST: sod123lf,SOD123; HEIGHT: 1.0 MM; MFG_NAME01: JSCJ-ELEC; Polyhex_Number: PD.020.0003; ROHS: Yes
J4 = USB_3P0_Standard-A: CON 9 USB 3.0 SKT RA TH TYPE A 2MM SP 330H AU 118L; AGILE_PN: 210-82091; CAD_APPROVED: Yes; HEIGHT: 8.38MM; MFG_NAME01: WENZHANGJIMEI; MFG_PN01: U30130140; Polyhex_Number: PD.011.0167; ROHS: Yes; Temp Range: -55°C ~ +105°C
R198 = RES: RES MF 1K 1/16W 5% 0402; ASSY_OPT: DNP; CAD_APPROVED: Yes; HEIGHT: 0.4 MM; MFG_NAME01: YAGEO; MFG_PN01: RC0402JR-071KL; Polyhex_Number: PD.004.0007; ROHS: Yes; Tolerance: 5%
R202 = RES: RES MF 10K 1/16W 5% 0402; AGILE_PN: 470-75557; ASSY_OPT: DNP; CAD_APPROVED: Yes; FPLIST: RC0402_25,RC0402_HD,0402_CC; HEIGHT: 0.4 MM; MFG_NAME01: YAGEO; MFG_PN01: RC0402JR-0710KL; Polyhex_Number: PD.004.0010; ROHS: Yes; Tolerance: 5%; VOLTAGE: 50V
R203 = RES: RES MF 51K 1/16W 5% 0402; CAD_APPROVED: Yes; HEIGHT: 0.23mm; MFG_NAME01: YAGEO; MFG_PN01: RC0402FR-0751KL; Polyhex_Number: PD.004.0184; ROHS: Yes; Tolerance: 5%; VOLTAGE: 50V
U21 = PCMF2USB3S_10P: IC EMI FILTER FOR DIFF CH W/ ESD PROTECTION 5V WLCSP10; AGILE_PN: 315-81227; CAD_APPROVED: Yes; HEIGHT: 0.6MM; MFG_NAME01: NEXPERIA; Polyhex_Number: PD.008.0312; ROHS: Yes; VOLTAGE: 5V
U23 = NX5P3290_WLCSP16: IC SW PWR CURRENT LIMITER ADJ 0.4-3.3A 4-5.5V WLCSP16; AGILE_PN: 315-82308; CAD_APPROVED: Yes; HEIGHT: 0.595MM; MFG_NAME01: NXP SEMICONDUCTORS; Polyhex_Number: PD.008.0314; ROHS: Yes; Temp Range: -40°C ~ 85°C; Temp_Range: -40°C ~ 85°C; VOLTAGE: 4-5.5V
C261 C271 C280 C291 = CAP_NP: CAP CER 10UF 6.3V 20% X5R 0402; AGILE_PN: 150-79163; CAD_APPROVED: Yes; FPLIST: CC0402_25,CC0402_HD,0402_CC; HEIGHT: 0.65 MM; MFG_NAME01: SAMSUNG; MFG_PN01: CL05A106MQ5NUNC; Polyhex_Number: PD.005.0031; ROHS: Yes; Tolerance: 20%; VOLTAGE: 6.3V
C263 C267 C282 C286 = CAP_NP: CAP CER 1uF 6.3V 10% X5R 0201; AGILE_PN: 150-79407; CAD_APPROVED: Yes; FPLIST: CC0201,CC0201_HD,0201_CC,0201_CC_012SM_NSP; HEIGHT: 0.35MM; MFG_NAME01: SAMSUNG; MFG_PN01: CL03A105KQ3CSNH; Package Size: 0201; Package Type: 7” reel; Polyhex_Number: PD.005.0030; ROHS: Yes; Tolerance: 10%; VOLTAGE: 6.3V
C274 C293 = CAP_NP: CAP CER 1500pF 2KV 10% X7R 1206; CAD_APPROVED: Yes; HEIGHT: 0.55 MM; MFG_NAME01: FHCOMP; MFG_PN01: 1206B152K202NT; Package Size: 1206; Polyhex_Number: PD.005.0012; ROHS: Yes; Tolerance: 10%; VOLTAGE: 2KV
C275 C278 C279 C294 C297 C298 = CAP_NP: CAP CER 18pF 50V 5% C0G 0201; CAD_APPROVED: Yes; HEIGHT: 0.35MM; MFG_NAME01: SAMSUNG; MFG_PN01: CL03C180JB3NNNH; Package Size: 0201; Package Type: 7” reel; Polyhex_Number: PD.005.0033; ROHS: Yes; Tolerance: 5%; VOLTAGE: 50V
C276 C277 C295 C296 = CAP_NP: CAP CER 0.022uF 16V 10% X5R 0402; CAD_APPROVED: Yes; FPLIST: CC0402_25,CC0402_HD,0402_CC,capc0402_l; HEIGHT: 0.55 MM; MFG_NAME01: SAMSUNG; MFG_PN01: CL05B223KO5NNNC; Package Size: 0402; Polyhex_Number: PD.005.0010; ROHS: Yes; Tolerance: 10%; VOLTAGE: 16V
FB2-FB6 FB8 FB9 = Ferrite_Bead: FERRITE 0402 120Ohm@100MHz 2A; HEIGHT: 0.5mm; Irms: <Irms>; MFG_NAME01: Murata; Polyhex_Number: PD.009.0006; Temp Range: -55C to +125C; Temp_Range: -55C to +125C
J5 = RJ45_1000_POE_0: CON RJ45 1000BASE TAB-DOWN LEFT-GREEN RIGHT-YELLOW POE DIP; HEIGHT: 13.65mm; MFG_NAME01: EVERCOM_HENGLIAN; Polyhex_Number: PD.011.0043; Temp Range: 0 to +70C; Temp_Range: 0 to +70C
J6 = CONN_HDR_2X2: CON HEADER 2X2PIN 2.54MM DIP; MFG_NAME01: WENZHANGJIMEI; MFG_PN01: PH2.54X2.5_2X2P_DIP; Polyhex_Number: PD.011.0056
L14 L15 = INDUCTORS_OF_FERRITE: IND PWR 2.2uH@1MHz Isat=2.07A Irms=1.25A 20% 2.5*2.0*1.2mm; Created by: YTL; DC Resistor: 0.216ohm; Irms: 1.6A; Isat: 2.0A; MFG_NAME01: SUNLORD; Part Type: POWER_IND; Polyhex_Number: PD.012.0054; Priority: A; Resonace frequency: 86M; Tolerance: 20%
R205-R210 R213 R214 R216 R217 R232-R237 R241 R242 R244 R245 = RES: RES MF ZERO OHM 1/20W 5% 0201; AGILE_PN: 470-82323; CAD_APPROVED: Yes; FPLIST: RC0201,0201_CC; HEIGHT: 0.26MM; MFG_NAME01: YAGEO; MFG_PN01: RC0201JR-070RL; Polyhex_Number: PD.004.0171; ROHS: Yes; Temp Range: -55°C ~ 125°C; Temp_Range: -55°C ~ 125°C; Tolerance: 5%; VOLTAGE: 25V
R211 R212 R238 R239 = RES: RES MF 10K 1/20W 5% 0201; CAD_APPROVED: Yes; HEIGHT: 0.23mm; MFG_NAME01: YAGEO; MFG_PN01: RC0201JR-0710KL; Polyhex_Number: PD.004.0069; ROHS: Yes; Tolerance: 5%; VOLTAGE: 25V
R215 R240 = RES: RES MF 1M 1/4W 1% 1206; CAD_APPROVED: Yes; HEIGHT: 0.23mm; MFG_NAME01: YAGEO; MFG_PN01: RC1206FR-071ML; Polyhex_Number: PD.004.0321; ROHS: Yes; Tolerance: 1%
R218 R220 R243 R246 = RES: RES MF 510R 1/20W 5% 0201; CAD_APPROVED: Yes; HEIGHT: 0.23mm; MFG_NAME01: YAGEO; MFG_PN01: RC0201JR-07510RL; Polyhex_Number: PD.004.0206; ROHS: Yes; Tolerance: 5%; VOLTAGE: 25V
R219 R247 = RES: RES MF 2K49 1/16W 1% 0402; CAD_APPROVED: Yes; HEIGHT: 0.23mm; MFG_NAME01: YAGEO; MFG_PN01: RC0402FR-072K49L; Polyhex_Number: PD.004.0145; ROHS: Yes; Tolerance: 1%; VOLTAGE: 50V
R221-R224 R226-R229 R231 R249 R250 R252 R254-R259 = RES: RES MF 4K7 1/20W 5% 0201; AGILE_PN: 470-82323; CAD_APPROVED: Yes; FPLIST: RC0201,0201_CC; HEIGHT: 0.26MM; MFG_NAME01: YAGEO; MFG_PN01: RC0201JR-074K7L; Polyhex_Number: PD.004.0072; ROHS: Yes; Temp Range: -55°C ~ 125°C; Temp_Range: -55°C ~ 125°C; Tolerance: 5%; VOLTAGE: 25V
R225 R253 = RES: RES MF 2K2 1/16W 5% 0402; CAD_APPROVED: Yes; HEIGHT: 0.23mm; MFG_NAME01: YAGEO; MFG_PN01: RC0402JR-072K2L; Polyhex_Number: PD.004.0098; ROHS: Yes; Tolerance: 5%; VOLTAGE: 50V
R230 R248 R251 R260 = RES: RES MF 4K7 1/20W 5% 0201; AGILE_PN: 470-82323; ASSY_OPT: DNP; CAD_APPROVED: Yes; FPLIST: RC0201,0201_CC; HEIGHT: 0.26MM; MFG_NAME01: YAGEO; MFG_PN01: RC0201JR-074K7L; Polyhex_Number: PD.004.0072; ROHS: Yes; Temp Range: -55°C ~ 125°C; Temp_Range: -55°C ~ 125°C; Tolerance: 5%; VOLTAGE: 25V
U24 U27 = YT8521SH-CA: INTEGRATED 10/100/1000M GIGABIT ETHERNET; HEIGHT: 0.85mm; MFG_NAME01: MotorComm; Polyhex_Number: PD.008.0315; Temp Range: -40C to +85C; Temp_Range: -40C to +85C
U25 U26 U28 U29 = TVS_ARRAY: TVS Diode array for ESD Protection 0.65pF; AGILE_PN: 480-79837; CAD_APPROVED: Yes; EN: 301-0-01726; HEIGHT: 0.5MM; MFG_NAME01: Jiejie Microelectronics; Polyhex_Number: PD.020.0022; ROHS: Yes; Temp Range: -55C to +125C; Temp_Range: -55C to +125C
Y2 = XTAL_13Y: XTAL 25MHZ 12pF 10PPM SMT 3.2X2.5MM; AGILE_PN: 230-77392; CAD_APPROVED: Yes; HEIGHT: 0.60MM; MFG_NAME01: HOSONIC; MFG_PN01: E3SB25E00000VE; Polyhex_Number: PD.018.0004; ROHS: Yes; Tolerance: 10PPM
FB7 = Ferrite_Bead: FERRITE 0402 120Ohm@100MHz 2A; ASSY_OPT: DNP; HEIGHT: 0.5mm; Irms: <Irms>; MFG_NAME01: Murata; Polyhex_Number: PD.009.0006; Temp Range: -55C to +125C; Temp_Range: -55C to +125C
J7 = RJ45_0: CON RJ45 1000BASE TAB-DOWN LEFT-GREEN RIGHT-YELLOW DIP; MFG_NAME01: EVERCOM_HENGLIAN; Polyhex_Number: PD.011.0119
Y3 = XTAL_13Y: XTAL 25MHZ 12pF 10PPM SMT 3.2X2.5MM; AGILE_PN: 230-77392; CAD_APPROVED: Yes; HEIGHT: 0.60MM; MFG_NAME01: HOSONIC; MFG_PN01: E3SB25E00000VE; Polyhex_Number: PD.018.0004; ROHS: Yes

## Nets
GND: C237.2 C238.2 C239.2 C240.2 C241.2 C242.2 C244.2 C245.2 C246.2 C247.2 C248.2 C249.2 C250.2 C255.2 C258.2 C259.2 C260.2 C261.2 C262.2 C263.2 C264.2 C265.2 C266.2 C267.2 C268.2 C269.2 C270.2 C271.2 C272.2 C273.2 C274.1 C275.2 C276.2 C277.2 C278.2 C279.2 C280.2 C281.2 C282.2 C283.2 C284.2 C285.2 C286.2 C287.2 C288.2 C289.2 C290.2 C291.2 C292.2 C293.1 C294.2 C295.2 C296.2 C297.2 C298.2 D6.A(ANODE) J3.1(SH1) J3.2(SH2) J3.3(SH3) J3.4(SH4) J3.A1(AGND1) J3.A12(AGND2) J3.B1(BGND1) J3.B12(BGND2) J4.4(GND) J4.7(GND_DRAIN) J4.S1(G1) J4.S2(G2) Q24.2(SOURCE) R177.2 R178.2 R179.2 R184.2 R185.1 R196.2 R197.2 R203.2 R215.1 R218.2 R219.2 R220.2 R222.2 R223.2 R224.2 R226.2 R227.2 R229.2 R231.1 R240.1 R243.2 R247.2 R249.2 R251.2 R252.2 R254.2 R255.2 R256.2 R257.2 R260.2 R630.2 U13.2(V-) U14.A4(GND1) U14.B2(GND2) U14.B3(GND3) U14.B4(GND4) U14.B5(GND5) U15.5(SLV_ADDR) U15.17(GND) U16.B1(GND) U17.B1(GND_CH1) U17.B2(GND_CH2) U18.5(GND1) U18.11(GND2) U18.20(GND3) U18.21(EPAD) U19.B1(GND_CH1) U19.B2(GND_CH2) U20.B3(GND) U20.D3(SBUEN) U21.B1(GND_CH1) U21.B2(GND_CH2) U22.B1(GND) U23.B3(GND1) U23.C3(GND2) U23.D3(GND3) U24.49(GND) U25.3(GND1) U25.8(GND2) U26.3(GND1) U26.8(GND2) U27.49(GND) U28.3(GND1) U28.8(GND2) U29.3(GND1) U29.8(GND2) Y2.2 Y2.4 Y3.2 Y3.4 ; also on sheet 4 5 7 8 9 10 11 12 17 18 19 20 21 22 23 24 25 26 27
GND_ETH1: C274.2 C293.2 J5.19 J5.20 J7.S1 J7.S2 R215.2 R240.2
VBUS_IN: C239.1 R180.2 R181.2 ; also on sheet 11 12 20
VDD_1V8: FB7.1 R253.1 ; also on sheet 4 5 6 9 10 12 18 21 22 23 24 25 26 27
VDD_3V3: C247.1 C249.1 C250.1 FB2.1 FB3.1 FB5.1 FB6.1 FB9.1 R174.1 R187.1 R189.1 R198.1 R201.1 R202.1 R211.1 R212.1 R225.1 R632.1 U15.3(VDD) U18.1(VDD1) U18.6(VDD2) U18.10(VDD3) ; also on sheet 4 10 11 12 17 18 20 22 24 26 27
VDD_5V: C248.1 D29.A U15.12(VCONN_IN) ; also on sheet 11 12 18 19 20 24 27
BYPASS1: C245.1 U15.4(BYPASS)
DBG_ACC: TP71.1(Pin1) U15.9(DBG_ACC)
DCDC_5V: C240.1 C241.1 C258.1 U14.D2(V5V_1) U14.D3(V5V_5) U14.E2(V5V_2) U14.E3(V5V_6) U14.F2(V5V_3) U14.F3(V5V_7) U14.G2(V5V_4) U14.G3(V5V_8) U23.A1(VIN1) U23.A2(VIN2) ; also on sheet 10 11 17
EN_SNK1: Q24.3(DRAIN) R182.2 R630.1 U14.F1(EN_SNK)
EN_SRC1: R183.2 U14.G1(EN_SRC)
ENET1_AVDD3: C267.1 C268.1 FB3.2 U24.1(AVDD33) U24.12(AVDD33_2)
ENET1_AVDDL: C264.1 C265.1 C269.1 FB4.2 U24.4(AVDDL_1) U24.9(AVDDL_2) U24.47(AVDDL_3)
ENET1_DVDD3: C261.1 C262.1 FB5.2 R221.1 R230.2 U24.30(DVDD33) U24.31(VDD33_LX)
ENET1_DVDD_RGMII: C263.1 C266.1 FB2.2 R228.1 U24.29(DVDD_RGMII)
ENET1_DVDDL: C271.1 C272.1 FB4.1 L14.2 U24.22(DVDDL)
ENET1_INT: R211.2 R214.1 U24.34(INT_N/PME_N)
ENET1_MDC: U24.14(MDC) ; also on sheet 6
ENET1_MDIO: R225.2 U24.15(MDIO) ; also on sheet 6
ENET1_MODE0: R207.1 R224.1 U24.25(RXD1/CFG_MODE0)
ENET1_MODE1: R205.1 R226.1 U24.24(RXD2/CFG_MODE1)
ENET1_MODE2: R206.1 R227.1 U24.23(RXD3/CFG_MODE2)
ENET1_nINT: R214.2 ; also on sheet 6
ENET1_nRST: R213.1 ; also on sheet 6
ENET1_PHYAD1: R210.1 R222.1 U24.28(RX_CLK/PHYAD1)
ENET1_PHYAD2: R208.1 R223.1 U24.27(RX_CTL/PHYAD2)
ENET1_RD0: R209.2 ; also on sheet 6
ENET1_RD1: R207.2 ; also on sheet 6
ENET1_RD2: R205.2 ; also on sheet 6
ENET1_RD3: R206.2 ; also on sheet 6
ENET1_RST: R212.2 R213.2 U24.13(RESET_N)
ENET1_RX_CTL: R208.2 ; also on sheet 6
ENET1_RXC: R210.2 ; also on sheet 6
ENET1_RXDLY: R209.1 R228.2 U24.26(RXD0/RXDLY)
ENET1_TD0: U24.19(TXD0) ; also on sheet 6
ENET1_TD1: U24.18(TXD1) ; also on sheet 6
ENET1_TD2: U24.17(TXD2) ; also on sheet 6
ENET1_TD3: U24.16(TXD3) ; also on sheet 6
ENET1_TRXN0: J5.2(TD-) U24.3(TRXN0) U26.2(CH2) U26.9(NC3)
ENET1_TRXN1: J5.6(TD2-) U24.6(TRXN1) U26.5(CH4) U26.6(NC1)
ENET1_TRXN2: J5.8(TD3-) U24.8(TRXN2) U25.2(CH2) U25.9(NC3)
ENET1_TRXN3: J5.10(TD4-) U24.11(TRXN3) U25.5(CH4) U25.6(NC1)
ENET1_TRXP0: J5.1(TD1+) U24.2(TRXP0) U26.1(CH1) U26.10(NC4)
ENET1_TRXP1: J5.3(TD2+) U24.5(TRXP1) U26.4(CH3) U26.7(NC2)
ENET1_TRXP2: J5.7(TD3+) U24.7(TRXP2) U25.1(CH1) U25.10(NC4)
ENET1_TRXP3: J5.9(TD4+) U24.10(TRXP3) U25.4(CH3) U25.7(NC2)
ENET1_TX_CTL: U24.20(TX_CTL) ; also on sheet 6
ENET1_TXC: U24.21(TX_CLK) ; also on sheet 6
ENET2_AVDD3: C286.1 C287.1 FB9.2 U27.1(AVDD33) U27.12(AVDD33_2)
ENET2_AVDDL: C284.1 C285.1 C288.1 FB8.2 U27.4(AVDDL_1) U27.9(AVDDL_2) U27.47(AVDDL_3)
ENET2_DVDD3: C280.1 C281.1 FB6.2 R238.1 R239.1 R246.1 R248.1 R259.1 U27.30(DVDD33) U27.31(VDD33_LX)
ENET2_DVDD_RGMII: C282.1 C283.1 FB7.2 R250.1 R258.1 U27.29(DVDD_RGMII)
ENET2_DVDDL: C289.1 C291.1 FB8.1 L15.2 U27.22(DVDDL)
ENET2_INT: R238.2 R242.1 U27.34(INT_N/PME_N)
ENET2_MODE0: R233.1 R254.1 U27.25(RXD1/CFG_MODE0)
ENET2_MODE1: R234.1 R255.1 U27.24(RXD2/CFG_MODE1)
ENET2_MODE2: R232.1 R256.1 U27.23(RXD3/CFG_MODE2)
ENET2_PHYAD1: R236.1 R250.2 R251.1 U27.28(RX_CLK/PHYAD1)
ENET2_PHYAD2: R237.1 R252.1 U27.27(RX_CTL/PHYAD2)
ENET2_RST: R239.2 R241.2 U27.13(RESET_N)
ENET2_RXDLY: R235.1 R258.2 U27.26(RXD0/RXDLY)
ENET2_TRXN0: J7.2(TD-) U27.3(TRXN0) U28.2(CH2) U28.9(NC3)
ENET2_TRXN1: J7.4(TD2-) U27.6(TRXN1) U28.5(CH4) U28.6(NC1)
ENET2_TRXN2: J7.8(TD3-) U27.8(TRXN2) U29.2(CH2) U29.9(NC3)
ENET2_TRXN3: J7.10(TD4-) U27.11(TRXN3) U29.5(CH4) U29.6(NC1)
ENET2_TRXP0: J7.1(TD1+) U27.2(TRXP0) U28.1(CH1) U28.10(NC4)
ENET2_TRXP1: J7.3(TD2+) U27.5(TRXP1) U28.4(CH3) U28.7(NC2)
ENET2_TRXP2: J7.7(TD3+) U27.7(TRXP2) U29.1(CH1) U29.10(NC4)
ENET2_TRXP3: J7.9(TD4+) U27.10(TRXP3) U29.4(CH3) U29.7(NC2)
ENET_MDC: U27.14(MDC) ; also on sheet 6
ENET_MDIO: R253.2 U27.15(MDIO) ; also on sheet 6
ENET_nINT_3V3: R242.2 ; also on sheet 26
ENET_nRST_3V3: R241.1 ; also on sheet 26
ENET_RD0: R235.2 ; also on sheet 6
ENET_RD1: R233.2 ; also on sheet 6
ENET_RD2: R234.2 ; also on sheet 6
ENET_RD3: R232.2 ; also on sheet 6
ENET_RX_CTL: R237.2 ; also on sheet 6
ENET_RXC: R236.2 ; also on sheet 6
ENET_TD0: U27.19(TXD0) ; also on sheet 6
ENET_TD1: U27.18(TXD1) ; also on sheet 6
ENET_TD2: U27.17(TXD2) ; also on sheet 6
ENET_TD3: U27.16(TXD3) ; also on sheet 6
ENET_TX_CTL: U27.20(TX_CTL) ; also on sheet 6
ENET_TXC: U27.21(TX_CLK) ; also on sheet 6
FRS_EN: U14.B6(FRS_EN) U15.1(FRS_EN)
I2C1_SCL_3V3: R191.1 R193.1 ; also on sheet 10 12
I2C1_SDA_3V3: R190.1 R192.1 ; also on sheet 10 12
ILIM_5V_VBUS: TP72.1(Pin1) U15.6(ILIM_5V_VBUS)
LD_I2C_SCL: R193.2 U14.B1(SCL)
LD_I2C_SDA: R192.2 U14.C1(SDA)
LD_nFLT: R187.2 R188.2 U15.11(FAULT_N)
LD_nINT: R188.1 U14.D1(~{INT})
NVCC_SD2: Q25.1(GATE) R631.1 ; also on sheet 4 6 10
NX5P_EN: R204.2 U23.B4(EN)
NX5P_FLT#: R201.2 U23.A4(~{FLT})
NX5P_FRS: R202.2 U23.C4(FO)
NX5P_ILIM: R203.1 U23.A3(ILIM)
PD_EN_SINK: Q24.1(GATE) ; also on sheet 12
PHY1_G_LED-: J5.16 R218.1
PHY1_LED0_PHYAD0: C275.1 R221.2 U24.35(LED0/PHYAD0)
PHY1_LED1_CFG_LDO0: C277.1 J5.15 R229.1 U24.36(LED1/CFG_LDO0)
PHY1_LED2_CFG_LDO1: C276.1 J5.17 R230.1 R231.2 U24.37(LED2/CFG_LDO1)
PHY1_XTAL_I: C279.1 R216.1 Y2.3
PHY1_XTAL_O: C278.1 R217.2 Y2.1
PHY1_Y_LED-: J5.18 R220.1
PHY2_G_LED-: J7.P12 R243.1
PHY2_LED0_PHYAD0: C294.1 R248.2 R249.1 U27.35(LED0/PHYAD0)
PHY2_LED1_CFG_LDO0: C296.1 J7.P11 R257.1 U27.36(LED1/CFG_LDO0)
PHY2_LED2_CFG_LDO1: C295.1 J7.P14 R259.2 R260.1 U27.37(LED2/CFG_LDO1)
PHY2_XTAL_I: C297.1 R245.1 Y3.3
PHY2_XTAL_O: C298.1 R244.2 Y3.1
PHY2_Y_LED+: J7.P13 R246.2
POE_TR0_TAP: J5.11(P11) J6.2(B1)
POE_TR1_TAP: J5.12(P12) J6.1(A1)
POE_TR2_TAP: J5.13(P13) J6.4(B2)
POE_TR3_TAP: J5.14(P14) J6.3(A2)
SS_RXN1: U17.C1(CH1_OUT+) U18.16(B1_N)
SS_RXN2: U18.12(C1_N) U19.C4(CH2_OUT-)
SS_RXP1: U17.C2(CH1_OUT-) U18.17(B1_P)
SS_RXP2: U18.13(C1_P) U19.C3(CH2_OUT+)
SS_TXN1: C252.2 U17.C3(CH2_OUT+)
SS_TXN2: C253.1 U19.C2(CH1_OUT-)
SS_TXP1: C251.2 U17.C4(CH2_OUT-)
SS_TXP2: C254.1 U19.C1(CH1_OUT+)
SSTXN1: C252.1 U18.18(B0_N)
SSTXN2: C253.2 U18.14(C0_N)
SSTXP1: C251.1 U18.19(B0_P)
SSTXP2: C254.2 U18.15(C0_P)
TCPC1_nINT: R189.2 U15.10(ALERT_N) ; also on sheet 6
USB1_CC1: R587.2 U15.13(CC1) U20.A2(CC1)
USB1_CC2: R588.2 U15.14(CC2) U20.B2(CC2) U20.C1(CON_SBU1) U20.C2(SBU1)
USB1_DN: U16.C1(CH1_OUT+) ; also on sheet 7
USB1_DP: U16.C2(CH1_OUT-) ; also on sheet 7
USB1_RXN: U18.8(A1_N) ; also on sheet 7
USB1_RXP: U18.7(A1_P) ; also on sheet 7
USB1_SS_SEL: R194.1 ; also on sheet 26
USB1_SS_XSD: Q25.2(SOURCE) R631.2 ; also on sheet 6
USB1_TXN: U18.4(A0_N) ; also on sheet 7
USB1_TXP: U18.3(A0_P) ; also on sheet 7
USB1_VBUS_3V3: R174.2 U13.1(OUT) ; also on sheet 7
USB1_VBUS_IN: C243.2 R180.1 R181.1 TP70.1(Pin1) U14.C6(VCHG1) U14.D6(VCHG2) U14.E6(VCHG3) U14.F6(VCHG4) U14.G6(VCHG5)
USB2_DN: R200.1 ; also on sheet 7 23
USB2_DP: R199.1 ; also on sheet 7 23
USB2_H_DN: R200.2 U22.C1(CH1_OUT+)
USB2_H_DP: R199.2 U22.C2(CH1_OUT-)
USB2_H_TXN: C257.2 U21.C2(CH1_OUT-)
USB2_H_TXP: C256.2 U21.C1(CH1_OUT+)
USB2_HOST_VBUS: C259.1 D7.C J4.1(VBUS) TP78.1(Pin1) U23.C2(VBUS3) U23.D1(VBUS1) U23.D2(VBUS2)
USB2_PWR_EN: R204.1 ; also on sheet 26
USB2_RXN: U21.C4(CH2_OUT-) ; also on sheet 7
USB2_RXP: U21.C3(CH2_OUT+) ; also on sheet 7
USB2_TXN: C257.1 ; also on sheet 7
USB2_TXP: C256.1 ; also on sheet 7
USB2_VBUS_3V3: R198.2 ; also on sheet 7
USB_HOST_DN: J4.2(D-) U22.A1(CH1_IN+)
USB_HOST_DP: J4.3(D+) U22.A2(CH1_IN-)
USB_HOST_RXN: J4.5(SSRX-) U21.A4(CH2_IN-)
USB_HOST_RXP: J4.6(SSRX+) U21.A3(CH2_IN+)
USB_HOST_TXN: J4.8(SSTX-) U21.A2(CH1_IN-)
USB_HOST_TXP: J4.9(SSTX+) U21.A1(CH1_IN+)
USBC_CC1: J3.A5(ACC1) R587.1 TP73.1(Pin1) U20.A1(CON_CC1)
USBC_CC2: J3.B5(BCC1) R588.1 TP74.1(Pin1) U20.B1(CON_CC2)
USBC_DN: J3.A7(ADN1) J3.B7(BDN1) U16.A1(CH1_IN+)
USBC_DP: J3.A6(ADP1) J3.B6(BDP1) U16.A2(CH1_IN-)
USBC_EN_SNK1: R182.1 U15.2(EN_SNK1)
USBC_EN_SRC1: R183.1 U15.16(EN_SRC)
USBC_I2C_SCL: R191.2 U15.8(I2C_SCL)
USBC_I2C_SDA: R190.2 U15.7(I2C_SDA)
USBC_SBU1: J3.A8(ASBU1) TP75.1(Pin1)
USBC_SBU2: J3.B8(BSBU1) TP76.1(Pin1)
USBC_SSRXN1: J3.B10(BSSRXN1) U17.A1(CH1_IN+)
USBC_SSRXN2: J3.A10(ASSRXN1) U19.A4(CH2_IN-)
USBC_SSRXP1: J3.B11(BSSRXP1) U17.A2(CH1_IN-)
USBC_SSRXP2: J3.A11(ASSRXP1) U19.A3(CH2_IN+)
USBC_SSTXN1: J3.A3(ASSTXN1) U17.A3(CH2_IN+)
USBC_SSTXN2: J3.B3(BSSTXN1) U19.A2(CH1_IN-)
USBC_SSTXP1: J3.A2(ASSTXP1) U17.A4(CH2_IN-)
USBC_SSTXP2: J3.B2(BSSTXP1) U19.A1(CH1_IN+)
USBC_VBUS_F: C238.1 F3.2 R175.1 R176.1 R177.1 U14.C2(VBUS1) U14.C3(VBUS2) U14.C4(VBUS3) U14.C5(VBUS4) U14.D4(VBUS5) U14.D5(VBUS6) U14.E4(VBUS7) U14.E5(VBUS8) U14.F4(VBUS9) U14.F5(VBUS10) U14.G4(VBUS11) U14.G5(VBUS12) U15.15(VBUS) ; also on sheet 12
VLDO1_3V3: C246.1 U14.A5(VLDO)
VLDO_3V3: C242.1 C255.1 R186.1 U14.A1(VDD) U20.A3(VSYS) ; also on sheet 12 24
N110548163: C237.1 D29.C(K) R173.1 U13.5(V+)
N110548244: R173.2 R179.1 U13.4(-IN)
N110548292: D6.C(CATHODE) R175.2 R176.2 R178.1 U13.3(+IN)
N110548769: C243.1 U14.A6(CAP2)
N110548786: C244.1 U14.A3(CAP1)
N110548843: R184.1 U14.A2(~{EN})
N110548849: R185.2 R186.2 U14.E1(ADDR)
N110550474: R194.2 R197.1 U18.9(SEL)
N110550489: R195.2 R196.1 U18.2(XSD)
N110560523: F3.1 J3.A4(AVBUS1) J3.A9(AVBUS2) J3.B4(BVBUS1) J3.B9(BVBUS2)
N110564487: C260.1 U23.D4(CAP)
N110564519: D7.A U23.B1(VCP1) U23.B2(VCP2) U23.C1(VCP3)
N110567055: L14.1 U24.32(LX)
N110567229: R219.1 U24.48(RBIAS)
N110567512: R217.1 U24.46(XTAL_O)
N110567514: R216.2 U24.45(XTAL_I)
N110570178: R245.2 U27.45(XTAL_I)
N110570199: R244.1 U27.46(XTAL_O)
N110717846: TP77.1(Pin1) U20.C3(FLAG)
N110805586: C273.1 J5.5(TCT2)
N110806168: C270.1 J5.4(TCT1)
N110833477: R247.1 U27.48(RBIAS)
N110833854: L15.1 U27.32(LX)
N110853484: C290.1 J7.5(TCT1)
N110853487: C292.1 J7.6(TCT2)
N111202580: Q25.3(DRAIN) R195.1 R632.2

Not connected (* = marked no-connect by the designer): J3 M1* M2*; U20 D1(CON_SBU2)* D2(SBU2)*; U24 33(Reserved_1)* 38(HSIP)* 39(HSIN)* 40(HSOP)* 41(HSON)* 42(NC)* 43(Reserved_2)* 44(CLKOUT)*; U27 33(Reserved_1)* 38(HSIP)* 39(HSIN)* 40(HSOP)* 41(HSON)* 42(NC)* 43(Reserved_2)* 44(CLKOUT)*

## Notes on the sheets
sheet 13
- USB2.0/3.0 C
- 0.9V
- For discharge
- VBUS DET
- De-bounce
- PWR SW OFF
- PWR SW ON
- Reboot
- #Set to 3.4A I2C CTRL
- # Use Always On Power(with VBUS), aviod entering Dead Battery Mode.
- OD
- I/OD
- #I2C ADDR: 0b'11100[01]x
- O
- O
- #default "L"
- O
- O/OD
- I2C_3.3V
- default "UFP" mode
- #I2C ADDR: 0b'1010000X
- True Table:
- PD_EN_SNK
- H
- USBC_EN_SNK1
- X
- EN_SNK1
- L
- Z:90 OHM
- L
- H
- H
- L
- L
- L
- Z:90 OHM
- Z:90 OHM
- # Crossbar Switch:
- #C1 C2 PIN used for layout convenient
- SEL=H, A-C
- CC OVP
- SEL=L, A-B as default
- XSD=H, disable
- XSD=L, enable as default
sheet 14
- USB3.0 HOST
- USB 3.0 HOST
- Note:
- USB2_VBUS_3V3 is not needed for HOST only port.
- 5V Source Load Switch
- -  0.4~3.3A -
- Rds=35 mOhm
  Vin=4.0~5.5V
- FO=0, Slew rate control(Internal 1M PD)
  FO=1, fast turn on
- RILM, ILIM = 51K, 0.9A
- EN=0, disable(Internal 1M PD); EN=1, enable
sheet 15
- DVDD33 Digital non-RGMII IO power
  VDD33_LX 3.3V power for switching regulator
  DVDD_RGMII Digital RGMII IO, MDC-MDIO power
  DVDDL Digital power 1.2V
  AVDD33 Analog Power 3.3V
  AVDDL Analog power 1.2V
- 3.3V
- PHY1_LED1_CFG_LDO0   Link  Green LED
- PHY1_LED2_CFG_LDO1   Activek  Yellow LED
- PHY_Address =001
- CFG_MODE[2:0]
- /RXD[3:1]
- Operation Mode
- 3'b000
- UTP<->RGMII
- 3'b001
- FIBER<->RGMII
- 3'b010
- 3'b011
- UTP/FIBER<->RGMII
- UTP<->SGMII
- 3'b100
- SGMII(PHY)<->RGMII
- 3'b101
- SGMII(MAC)<->RGMII
- 3'b110
- UTP<->FIBER(AUTO)
- 3'b111
- UTP<->FIBER(FORCE)
- /LED[2:1]
- CFG_LDO[1:0]
- RGMII Voltage
- 2'b00
- 3.3V_Extenal
- Mode "000" = 000 UTP<-> RGMII
- 2'b01
- 2.5V_Internal
- 2'b10
- 1.8V_Internal
- 2'b11
- -
- Mode Selection Pins
- Pin No
- Pin Name
- Default
- 23
- RXD3/CFG_MODE2
- 0
- 24
- RXD2/CFG_MODE1
- 0
- 25
- RXD1/CFG_MODE0
- 0
- 26
- 27
- RXD0/RXDLY
- RX_DV/PHYAD2
- 0
- 1
- 28
- RX_CLK/PHYAD1
- 0
- 35
- LED0/PHYAD0
- 1
- 36
- LED1/CFG_LDO0
- 0
- RGMII IO 3.3V
- 37
- LED2/CFG_LDO1
- 0
- Add 2ns delay to RX_CLK
- Link
- Active
- RXDLY
- CFG_LDO[1:0]
- YT8521SH-CA
- Pull up to add 2ns delay to RXC for RXD latching.
- YT8521SH-CA
- 2’b00: 3.3V
- 2’b01: 2.5V
- 2’b10: 1.8V
- 2b'11: 1.8V
- RTL8211FSI-CG
- Pull up to add 2ns delay to RXC for RXD latching.
- RTL8211FSI-CG
- 2’b00: 3.3V
- 2’b01: 2.5V
- 2’b10: 1.8V
- 2b'11: 1.5V
sheet 16
- 1.8V
- 1.8V
- PHY1_LED1_CFG_LDO0   Link  Green LED
- PHY1_LED2_CFG_LDO1   Activek  Yellow LED
- PHY_Address =010
- CFG_MODE[2:0]
- Operation Mode
- /RXD[3:1]
- 3'b000
- 3'b001
- FIBER<->RGMII
- UTP<->RGMII
- 3'b010
- UTP/FIBER<->RGMII
- 3'b011
- UTP<->SGMII
- 3'b100
- SGMII(PHY)<->RGMII
- 3'b101
- SGMII(MAC)<->RGMII
- 3'b110
- 3'b111
- UTP<->FIBER(AUTO)
- UTP<->FIBER(FORCE)
- CFG_LDO[1:0]
- /LED[2:1]
- RGMII Voltage
- 2'b00
- 3.3V_Extenal
- 2'b01
- 2.5V_Internal
- 2'b10
- 2'b11
- -
- 1.8V_Internal
- Mode "000" = 000 UTP<-> RGMII
- Mode Selection Pins
- Pin No
- Pin Name
- Default
- 23
- 24
- RXD2/CFG_MODE1
- RXD3/CFG_MODE2
- 0
- 0
- 25
- RXD1/CFG_MODE0
- 0
- 26
- RXD0/RXDLY
- 1
- Add 2ns delay to RX_CLK
- 27
- RX_DV/PHYAD2
- 0
- 28
- RX_CLK/PHYAD1
- 1
- 35
- LED0/PHYAD0
- 0
- RGMII IO 1.8V
- 36
- 37
- LED1/CFG_LDO0
- LED2/CFG_LDO1
- 0
- 1
- Link
- Active
- RXDLY
- CFG_LDO[1:0]
- YT8521SH-CA
- Pull up to add 2ns delay to RXC for RXD latching.
- YT8521SH-CA
- 2’b00: 3.3V
- 2’b01: 2.5V
- 2’b10: 1.8V
- 2b'11: 1.8V
- RTL8211FSI-CG
- Pull up to add 2ns delay to RXC for RXD latching.
- RTL8211FSI-CG
- 2’b00: 3.3V
- 2’b01: 2.5V
- 2’b10: 1.8V
- 2b'11: 1.5V
